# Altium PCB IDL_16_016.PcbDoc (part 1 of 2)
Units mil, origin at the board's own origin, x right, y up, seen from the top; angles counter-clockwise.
Board outline 4921.26 x 4921.26 mil, 4 copper layers (Top Layer - SIG1, MID1_GND, MID2_PWR, Bottom Layer - SIG2), stack 60.174 mil thick; 186 components, 167 nets, 650 pads, 188 vias.
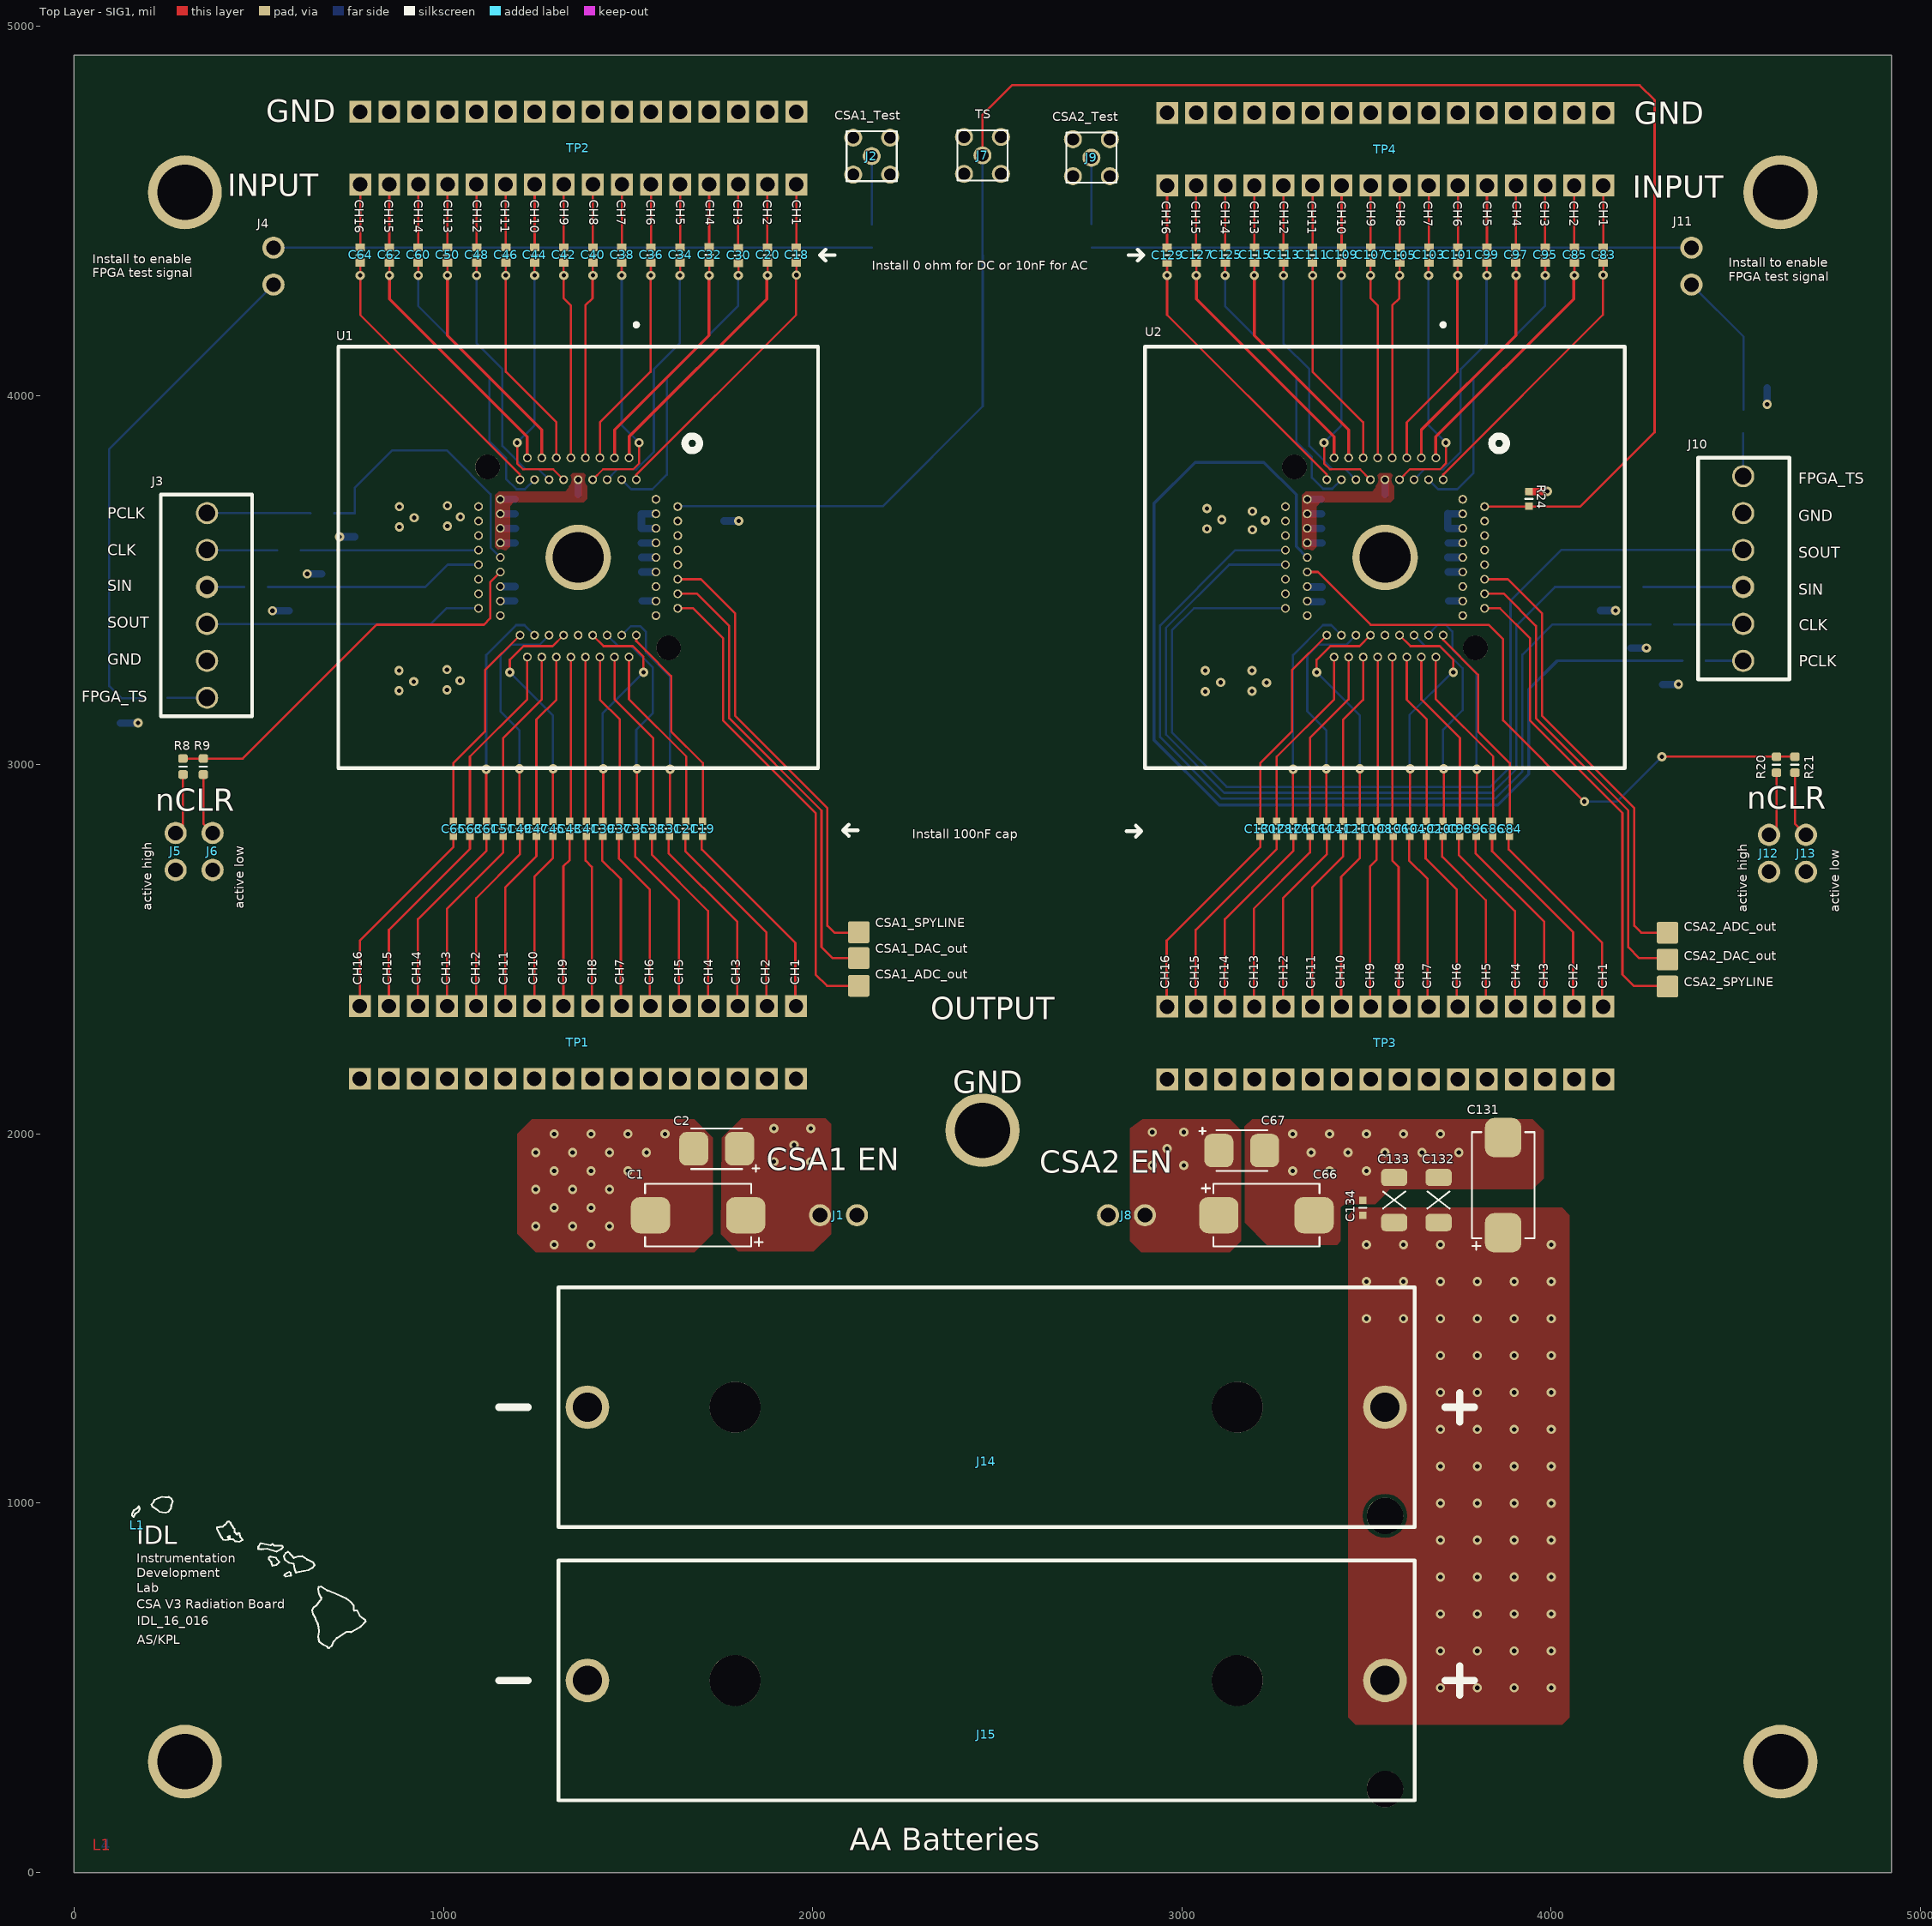
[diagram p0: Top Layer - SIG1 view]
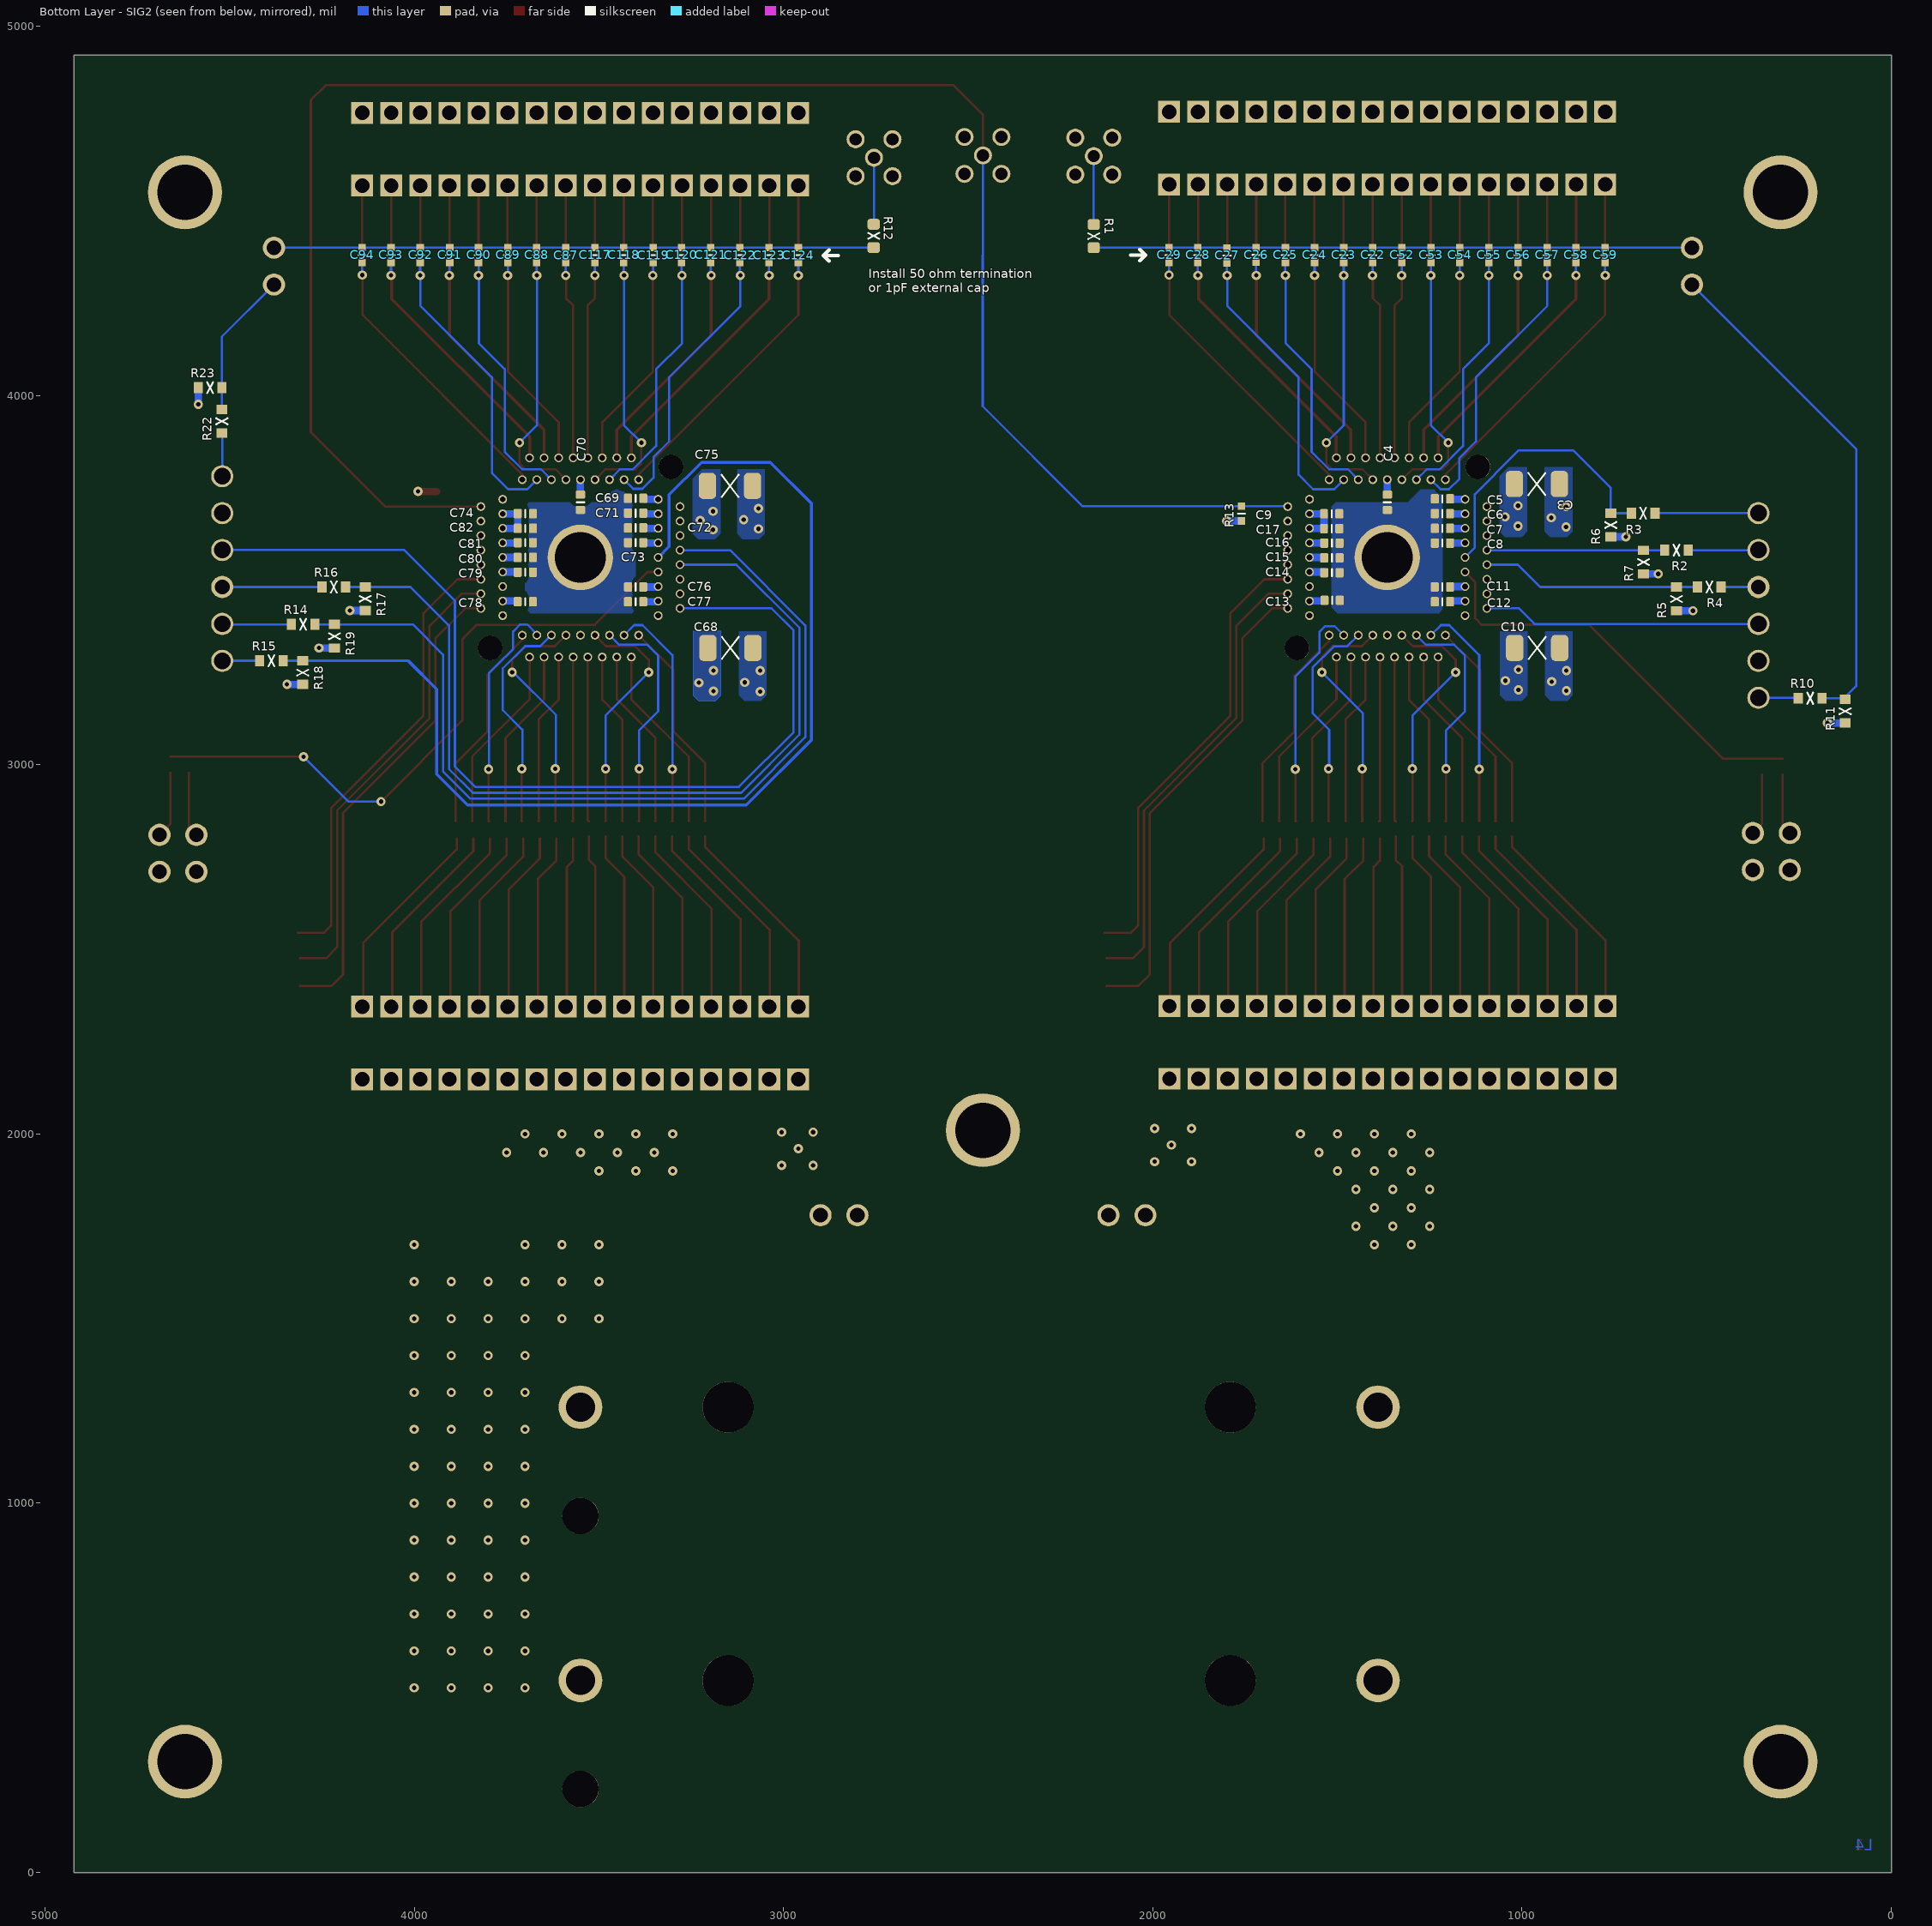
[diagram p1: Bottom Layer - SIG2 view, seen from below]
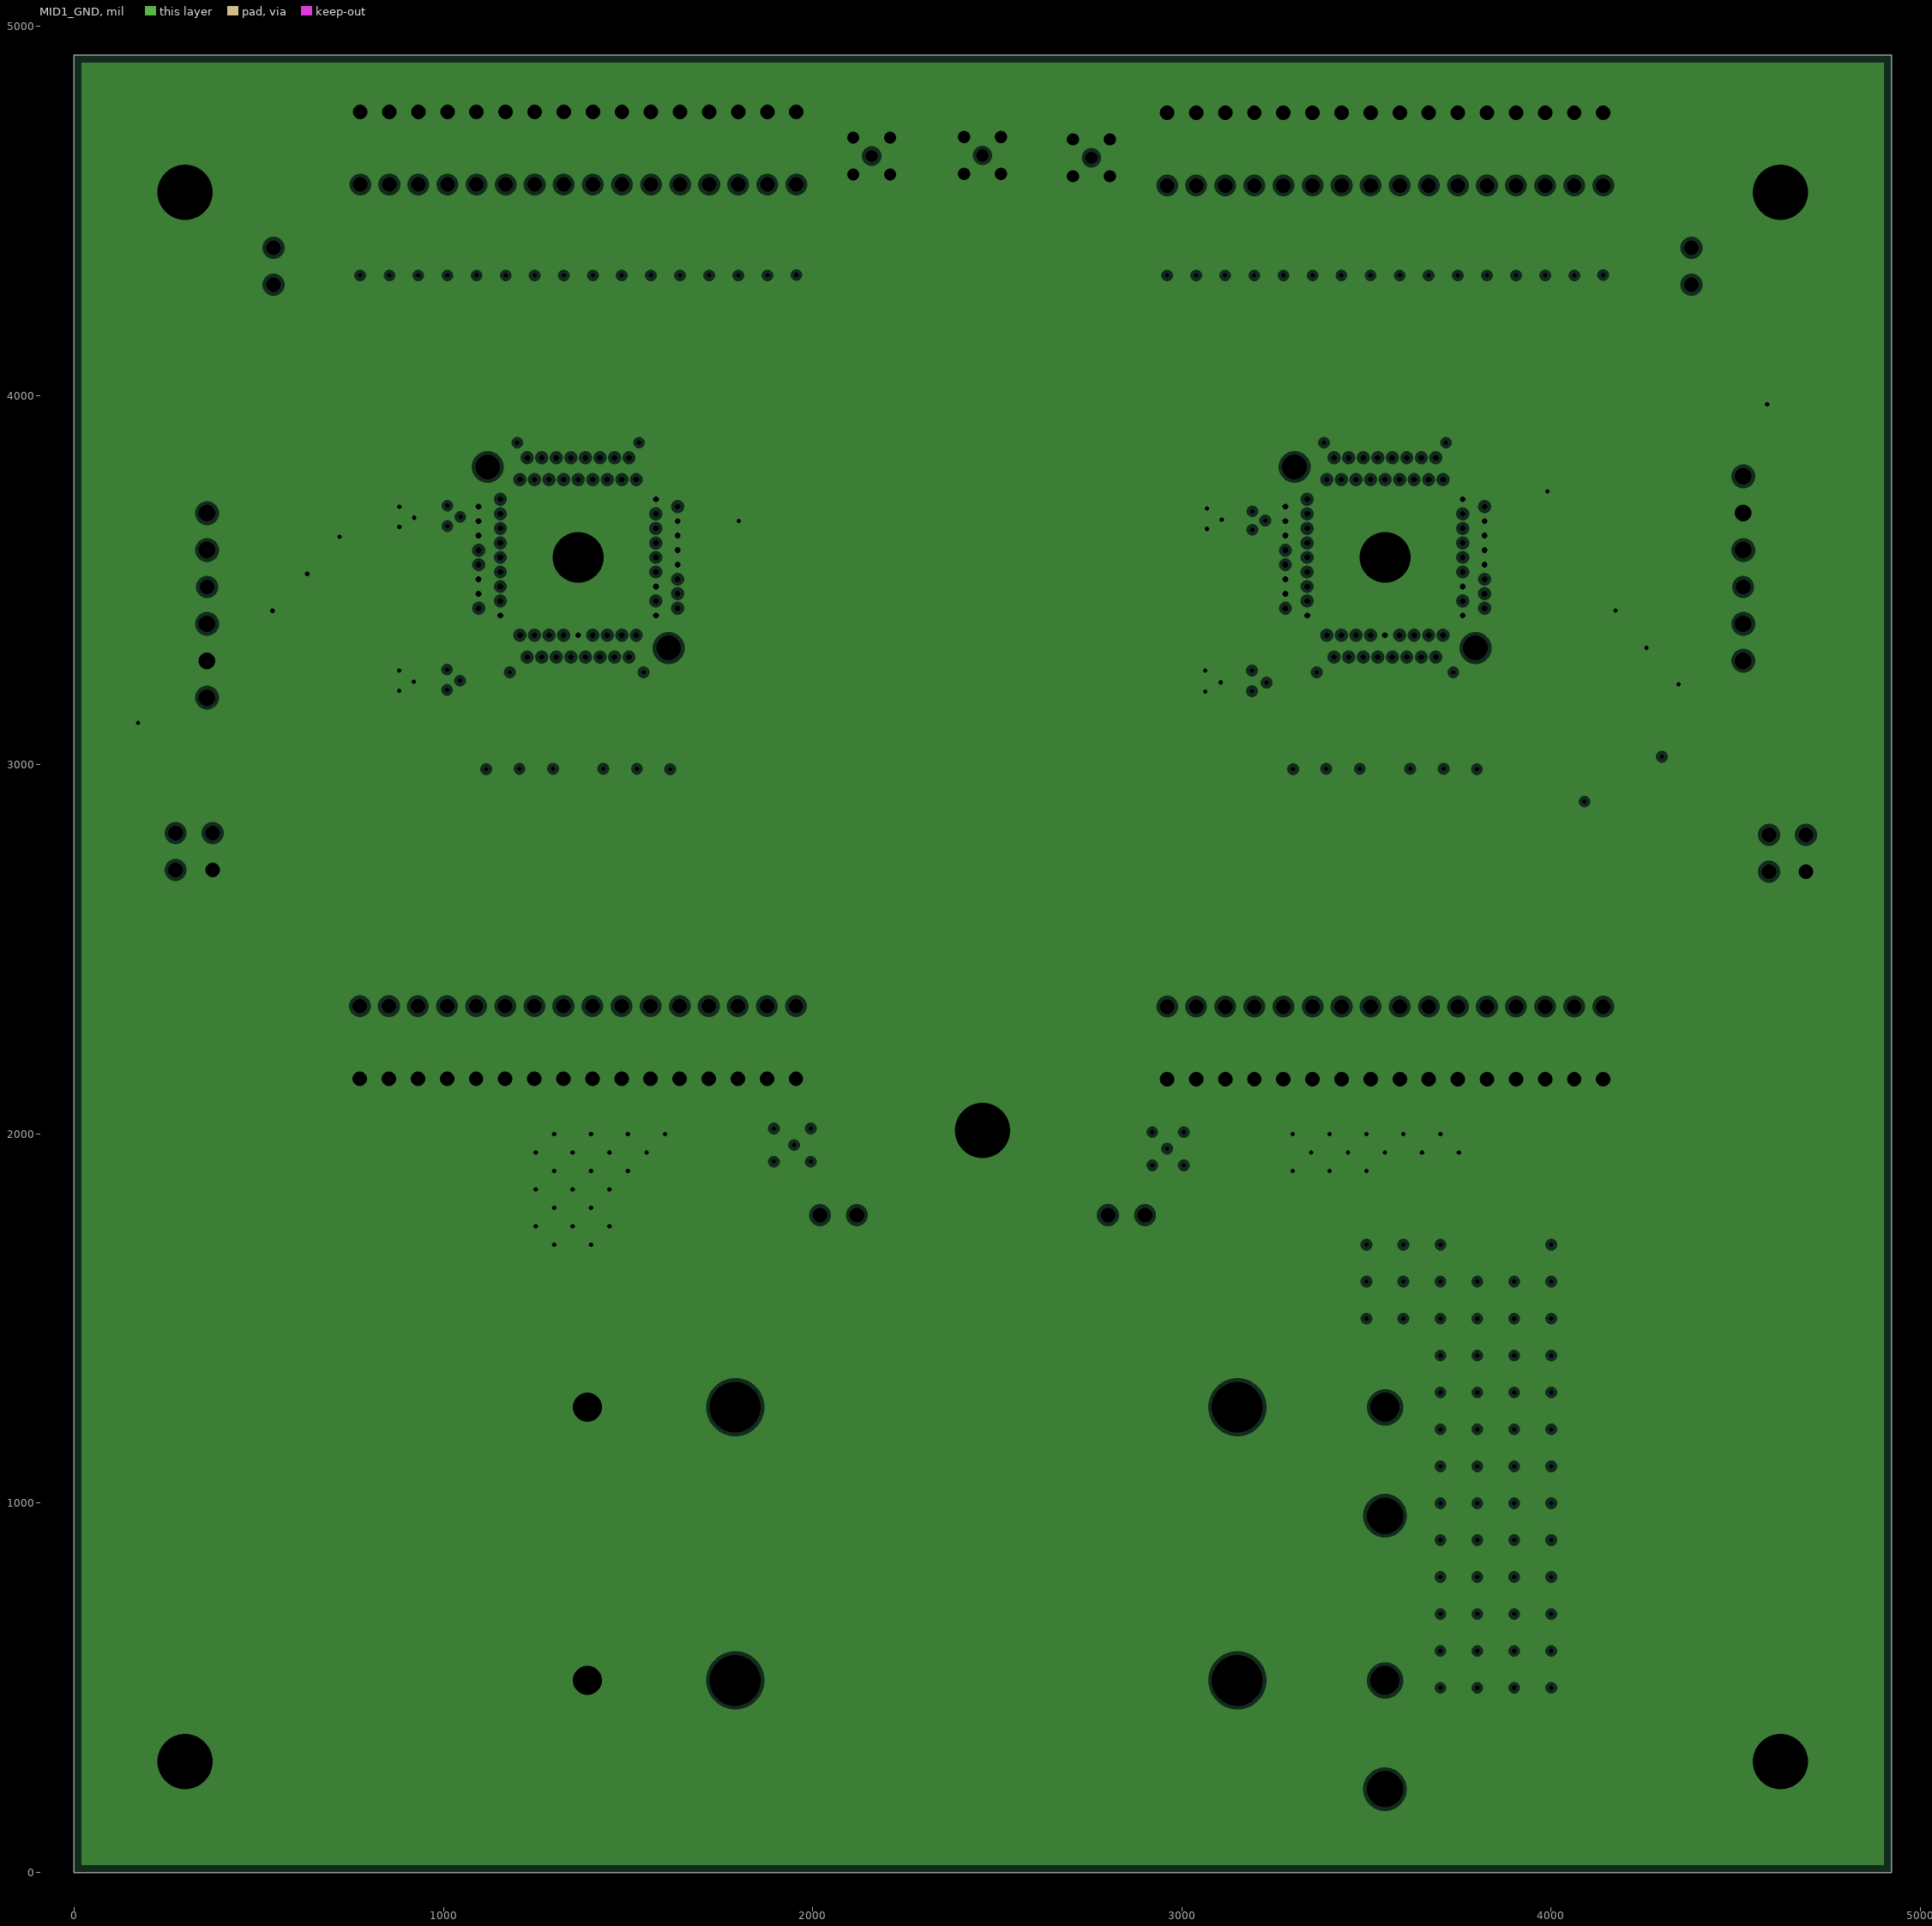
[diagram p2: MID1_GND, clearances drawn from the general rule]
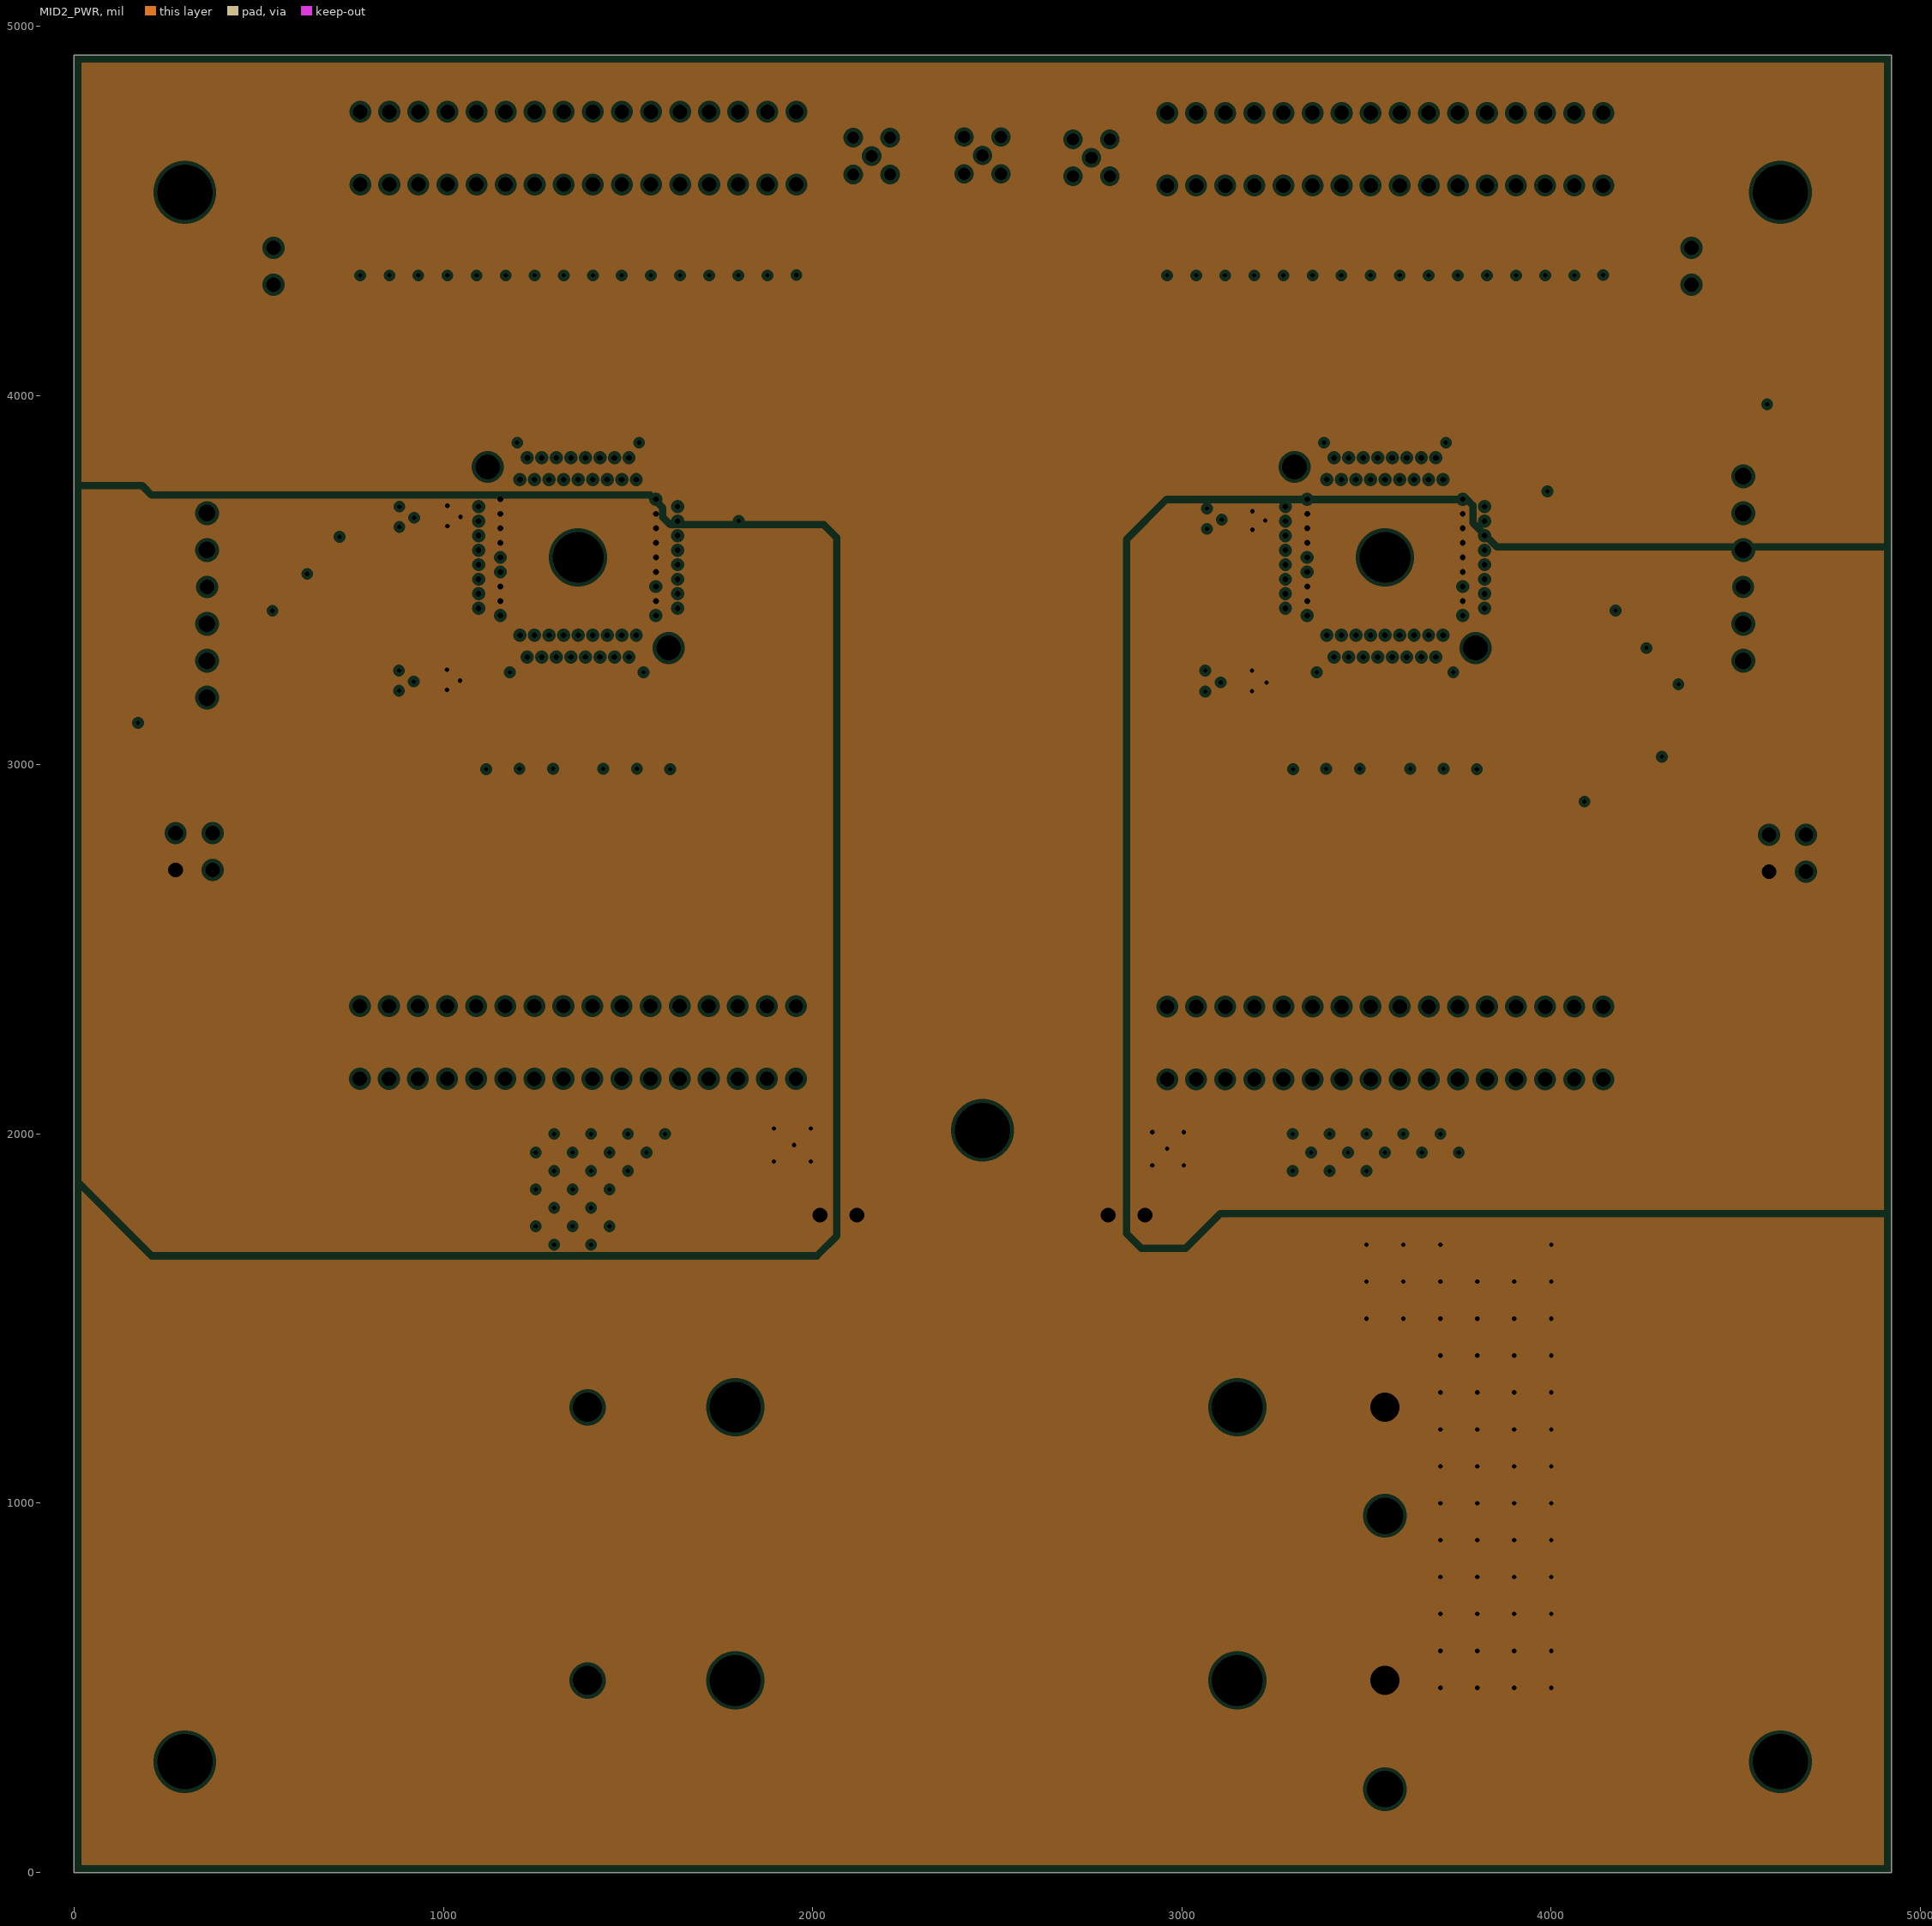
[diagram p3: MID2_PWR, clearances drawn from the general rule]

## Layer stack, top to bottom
Top Solder: solder mask 0.4, Solder Resist, Dk 3.5
Top Layer - SIG1: signal copper 1.378
Dielectric 1: prepreg 8, FR-4, Dk 4.65
MID1_GND: plane copper 0.709, net GND
Dielectric 2: core 40, FR-4, Dk 4.65
MID2_PWR: plane copper 0.709, net (Multiple Nets)
Dielectric 4: prepreg 8, FR-4, Dk 4.2
Bottom Layer - SIG2: signal copper 1.378
Bottom Solder: solder mask 0.4, Solder Resist, Dk 3.5

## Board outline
0,0 4921.26,0 4921.26,4921.26 0,4921.26

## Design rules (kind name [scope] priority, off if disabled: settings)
Clearance Clearance_Diff [InAnyDifferentialPair  or InNet('NetJ9_2') vs InNamedPolygon('Top_GND') or InNamedPolygon('Bot_GND3')] p1: gap=15
Clearance Clearance_RF [InNetClass('RF') or InNet('PWR') or InNet('NetJ9_2') or InNet('PWR1') or InNet('PWR2') vs InNamedPolygon('Top_GND') or InNamedPolygon('Bot_GND3')] p2: gap=20
Clearance Clearance_Poly [InNamedPolygon('L1_Top') or InNamedPolygon('L2_GND') or InNamedPolygon('L3_PWR') OR InNamedPolygon('L4_BOT')] p3: gap=10
Clearance Clearance_KeepOut [Iskeepout] p4 off: gap=20
Clearance [All] p5: gap=10
ComponentClearance [All] p1 off: gap=10 collisioncheckmode=3 verticalgap=10 showdistances=FALSE
DiffPairsRouting [All] p1: maxlimit=10 minlimit=6 mostfreqgap=6 toplayer_minwidth=6 toplayer_maxwidth=12 toplayer_prefwidth=8 bottomlayer_minwidth=6 bottomlayer_maxwidth=12 bottomlayer_prefwidth=8 maxuncoupledlength=500
Height [All] p1 off: minheight=0 maxheight=1000 prefheight=500
HoleSize [All] p1: absolutevalues=TRUE maxlimit=2500 minlimit=10 maxpercent=80.000 minpercent=20.000
MinimumSolderMaskSliver [All] p1: minsoldermaskwidth=5
NetAntennae [All] p1 off: netantennaetolerance=0
PlaneClearance [All] p1: clearance=10
PlaneConnect PlaneConnect_vIA [ISvIA] p1: planeconnectstyle=Direct reliefexpansion=20 reliefentries=4 reliefconductorwidth=10 reliefairgap=10
PlaneConnect [All] p2: planeconnectstyle=Direct reliefexpansion=12 reliefentries=4 reliefconductorwidth=15 reliefairgap=8
PolygonConnect PolygonConnect_Via [IsVia or InNet('GND') or InNet('PWR') or InNet('NetJ9_2') or InNet('PWR1') or InNet('PWR2')] p1: connectstyle=Direct reliefconductorwidth=10 reliefentries=4 polygonreliefangle="90 Angle" airgapwidth=10
PolygonConnect PolygonConnect_Main [All] p2: connectstyle=Relief reliefconductorwidth=12 reliefentries=4 polygonreliefangle="90 Angle" airgapwidth=10
RoutingVias [All] p1: holewidth=12 width=25 viastyle="Through Hole" minholewidth=6 minwidth=12 maxholewidth=25 maxwidth=50
SilkToSilkClearance [All] p1: silktosilkclearance=5
SilkToSolderMaskClearance SilkscreenOverComponentPads [IsPad] p1: minsilkscreentomaskgap=5 clearancetoexposedcopper=TRUE
SolderMaskExpansion [All] p1: expansion=2
Width Width_Logo [HasFootprint('ITECH_LOGO')] p1: maxlimit=10 minlimit=1 preferedwidth=2
Width [All] p2: maxlimit=150 minlimit=6 preferedwidth=8 minimp=50.000000 maximp=50.000000 favimp=50.000000
20 further rules are at their usual default settings.

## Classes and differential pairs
net class RF: CSA1_FPGA_TS CSA2_FPGA_TS GND NetC18_1 NetC18_2 NetC19_1 NetC19_2 NetC20_1 NetC20_2 NetC21_1 NetC21_2 NetC22_1 NetC23_1 NetC24_1 NetC25_1 NetC26_1 NetC27_1 NetC30_1 NetC31_1 NetC31_2 NetC32_1 NetC33_1 NetC33_2 NetC34_1 NetC35_1 NetC35_2 NetC36_1 NetC37_1 NetC37_2 NetC38_1 NetC39_1 NetC39_2 NetC40_1 NetC41_1 NetC41_2 NetC42_1 NetC42_2 NetC43_1 NetC43_2 NetC44_1 NetC44_2 NetC45_1 NetC45_2 NetC46_1 NetC46_2 NetC47_1 NetC47_2 NetC48_1 NetC48_2 NetC49_1 NetC49_2 NetC50_1 NetC50_2 NetC51_1 NetC51_2 NetC57_2 NetC58_2 NetC59_2 NetC60_1 NetC61_1 NetC61_2 NetC62_1 NetC63_1 NetC63_2 NetC64_1 NetC65_1 NetC65_2 NetC83_1 NetC83_2 NetC84_1 NetC84_2 NetC85_1 NetC85_2 NetC86_1 NetC86_2 NetC87_1 NetC88_1 NetC89_1 NetC90_1 NetC91_1 NetC92_1 NetC95_1 NetC96_1 NetC96_2 NetC97_1 NetC98_1 NetC98_2 NetC99_1 NetC100_1 NetC100_2 NetC101_1 NetC102_1 NetC102_2 NetC103_1 NetC104_1 NetC104_2 NetC105_1 NetC106_1 NetC106_2 NetC107_1 NetC107_2 NetC108_1 NetC108_2 NetC109_1 NetC109_2 NetC110_1 NetC110_2 NetC111_1 NetC111_2 NetC112_1 NetC112_2 NetC113_1 NetC113_2 NetC114_1 NetC114_2 NetC115_1 NetC115_2 NetC116_1 NetC116_2 NetC122_2 NetC123_2 NetC124_2 NetC125_1 NetC126_1 NetC126_2 NetC127_1 NetC128_1 NetC128_2 NetC129_1 NetC130_1 NetC130_2 NetJ2_1 NetJ9_1 "TEST SIGNAL"
component class CSAv3_A2_Socket2: C66 C67 C68 C69 C70 C71 C72 C73 C74 C75 C76 C77 C78 C79 C80 C81 C82 C83 C84 C85 C86 C87 C88 C89 C90 C91 C92 C93 C94 C95 C96 C97 C98 C99 C100 C101 C102 C103 C104 C105 C106 C107 C108 C109 C110 C111 C112 C113 C114 C115 C116 C117 C118 C119 C120 C121 C122 C123 C124 C125 C126 C127 C128 C129 C130 C131 C132 C133 C134 CSA2_ADC_out CSA2_DAC_out CSA2_SPYLINE J8 J9 J10 J11 J12 J13 J14 J15 R12 R13 R14 R15 R16 R17 R18 R19 R20 R21 R22 R23 TP3 TP4 U2
component class CSAv3_A1_Socket1: C1 C2 C3 C4 C5 C6 C7 C8 C9 C10 C11 C12 C13 C14 C15 C16 C17 C18 C19 C20 C21 C22 C23 C24 C25 C26 C27 C28 C29 C30 C31 C32 C33 C34 C35 C36 C37 C38 C39 C40 C41 C42 C43 C44 C45 C46 C47 C48 C49 C50 C51 C52 C53 C54 C55 C56 C57 C58 C59 C60 C61 C62 C63 C64 C65 CSA1_ADC_out J1 J2 J3 J4 J5 J6 J7 L1 R1 R2 R3 R4 R5 R6 R7 R8 R9 R10 R11 R24 TP1 TP2 U1

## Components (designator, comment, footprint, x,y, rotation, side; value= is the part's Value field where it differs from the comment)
C1 "220uF" CTC-D7343-43 1690,1780 r180 top
C2 "150uF" CTC-B3528-21 1740,1960 r180 top
C3 "10uF" CC1206N1R 960,3760 r180 bottom
C4 "4.7uF" CC0402N1R 1365,3710.59 r270 bottom
C5 "4.7uF" CC0402N1R 1215.67,3720 r0 bottom
C6 "4.7uF" CC0402N1R 1215.67,3680 r0 bottom
C7 "4.7uF" CC0402N1R 1215.67,3640 r0 bottom
C8 "4.7uF" CC0402N1R 1215.67,3600 r0 bottom
C9 "4.7uF" CC0402N1R 1515.63,3679.37 r180 bottom
C10 "10uF" CC1206N1R 958.98,3316.26 r0 bottom
C11 "4.7uF" CC0402N1R 1215.67,3481.26 r180 bottom
C12 "4.7uF" CC0402N1R 1215.67,3441.26 r180 bottom
C13 "4.7uF" CC0402N1R 1514.33,3445 r0 bottom
C14 "4.7uF" CC0402N1R 1515,3520 r0 bottom
C15 "4.7uF" CC0402N1R 1515,3560 r0 bottom
C16 "4.7uF" CC0402N1R 1515,3600 r0 bottom
C17 "4.7uF" CC0402N1R 1515.63,3639.37 r0 bottom
C18 "10nF" CC0402N1X 1956,4380 r270 top
C19 "100nF" CC0402RF1 1702,2826.26 r270 top
C20 "10nF" CC0402N1X 1878,4380 r270 top
C21 "100nF" CC0402RF1 1657,2826.26 r270 top
C22 "1.0pF" CC0402RF1 1405,4380 r90 bottom
C23 "1.0pF" CC0402RF1 1483,4380 r90 bottom
C24 "1.0pF" CC0402RF1 1562,4380 r90 bottom
C25 "1.0pF" CC0402RF1 1641,4380 r90 bottom
C26 "1.0pF" CC0402RF1 1720,4380.67 r90 bottom
C27 "1.0pF" CC0402RF1 1799,4379 r90 bottom
C28 "1.0pF" CC0402RF1 1878,4380 r90 bottom
C29 "1.0pF" CC0402RF1 1956,4380 r90 bottom
C30 "10nF" CC0402N1X 1799,4379 r270 top
C31 "100nF" CC0402RF1 1612,2826.26 r270 top
C32 "10nF" CC0402N1X 1720,4380.67 r270 top
C33 "100nF" CC0402RF1 1567,2826.26 r270 top
C34 "10nF" CC0402N1X 1641,4380 r270 top
C35 "100nF" CC0402RF1 1522,2826.26 r270 top
C36 "10nF" CC0402N1X 1562,4380 r270 top
C37 "100nF" CC0402RF1 1477,2826.26 r270 top
C38 "10nF" CC0402N1X 1483,4380 r270 top
C39 "100nF" CC0402RF1 1432,2826.26 r270 top
C40 "10nF" CC0402N1X 1405,4380 r270 top
C41 "100nF" CC0402RF1 1387,2826.26 r270 top
C42 "10nF" CC0402N1X 1326,4380.33 r270 top
C43 "100nF" CC0402RF1 1342,2826.26 r270 top
C44 "10nF" CC0402N1X 1247,4380 r270 top
C45 "100nF" CC0402RF1 1297,2826.26 r270 top
C46 "10nF" CC0402N1X 1169,4380 r270 top
C47 "100nF" CC0402RF1 1252,2826.26 r270 top
C48 "10nF" CC0402N1X 1090,4380 r270 top
C49 "100nF" CC0402RF1 1207,2826.26 r270 top
C50 "10nF" CC0402N1X 1011,4380 r270 top
C51 "100nF" CC0402RF1 1162,2826.26 r270 top
C52 "1.0pF" CC0402RF1 1326,4380 r270 bottom
C53 "1.0pF" CC0402RF1 1247,4380 r270 bottom
C54 "1.0pF" CC0402RF1 1169,4380 r270 bottom
C55 "1.0pF" CC0402RF1 1090,4380 r270 bottom
C56 "1.0pF" CC0402RF1 1011,4380 r270 bottom
C57 "1.0pF" CC0402RF1 932,4380 r270 bottom
C58 "1.0pF" CC0402RF1 854,4380 r270 bottom
C59 "1.0pF" CC0402RF1 775,4380 r270 bottom
C60 "10nF" CC0402N1X 932,4380 r270 top
C61 "100nF" CC0402RF1 1117,2826.26 r270 top
C62 "10nF" CC0402N1X 854,4380 r270 top
C63 "100nF" CC0402RF1 1072,2826.26 r270 top
C64 "10nF" CC0402N1X 775,4380 r270 top
C65 "100nF" CC0402RF1 1027,2826.26 r270 top
C66 "220uF" CTC-D7343-43 3228.94,1780 r0 top
C67 "150uF" CTC-B3528-21 3162.01,1955 r0 top
C68 "10uF" CC1206N1R 3143.98,3316.26 r180 bottom
C69 "4.7uF" CC0402N1R 3400.67,3721.26 r0 bottom
C70 "4.7uF" CC0402N1R 3550,3710.59 r270 bottom
C71 "4.7uF" CC0402N1R 3400.67,3681.26 r0 bottom
C72 "4.7uF" CC0402N1R 3400.67,3641.26 r0 bottom
C73 "4.7uF" CC0402N1R 3400.67,3601.26 r0 bottom
C74 "4.7uF" CC0402N1R 3699.33,3680 r180 bottom
C75 "10uF" CC1206N1R 3145,3755 r0 bottom
C76 "4.7uF" CC0402N1R 3400.67,3481.26 r180 bottom
C77 "4.7uF" CC0402N1R 3400.67,3441.26 r180 bottom
C78 "4.7uF" CC0402N1R 3699.33,3441.26 r0 bottom
C79 "4.7uF" CC0402N1R 3699.33,3521.26 r0 bottom
C80 "4.7uF" CC0402N1R 3699.33,3561.26 r0 bottom
C81 "4.7uF" CC0402N1R 3699.33,3601.26 r0 bottom
C82 "4.7uF" CC0402N1R 3699.33,3640 r0 bottom
C83 "10nF" CC0402N1X 4141,4380 r270 top
C84 "100nF" CC0402RF1 3887,2826.26 r270 top
C85 "10nF" CC0402N1X 4063,4380 r270 top
C86 "100nF" CC0402RF1 3842,2826.26 r270 top
C87 "1.0pF" CC0402RF1 3590,4379.92 r90 bottom
C88 "1.0pF" CC0402RF1 3669,4380 r90 bottom
C89 "1.0pF" CC0402RF1 3747,4380 r90 bottom
C90 "1.0pF" CC0402RF1 3826,4380 r90 bottom
C91 "1.0pF" CC0402RF1 3904,4380 r90 bottom
C92 "1.0pF" CC0402RF1 3984,4380 r90 bottom
C93 "1.0pF" CC0402RF1 4063,4380 r90 bottom
C94 "1.0pF" CC0402RF1 4141,4380 r90 bottom
C95 "10nF" CC0402N1X 3984,4380 r270 top
C96 "100nF" CC0402RF1 3797,2826.26 r270 top
C97 "10nF" CC0402N1X 3904,4380 r270 top
C98 "100nF" CC0402RF1 3752,2826.26 r270 top
C99 "10nF" CC0402N1X 3826,4380 r270 top
C100 "100nF" CC0402RF1 3707,2826.26 r270 top
C101 "10nF" CC0402N1X 3747,4380 r270 top
C102 "100nF" CC0402RF1 3662,2826.26 r270 top
C103 "10nF" CC0402N1X 3669,4380 r270 top
C104 "100nF" CC0402RF1 3617,2826.26 r270 top
C105 "10nF" CC0402N1X 3590,4379.92 r270 top
C106 "100nF" CC0402RF1 3572,2826.26 r270 top
C107 "10nF" CC0402N1X 3511,4380 r270 top
C108 "100nF" CC0402RF1 3527,2826.26 r270 top
C109 "10nF" CC0402N1X 3433,4380 r270 top
C110 "100nF" CC0402RF1 3482,2826.26 r270 top
C111 "10nF" CC0402N1X 3353,4380 r270 top
C112 "100nF" CC0402RF1 3437,2826.26 r270 top
C113 "10nF" CC0402N1X 3276,4380 r270 top
C114 "100nF" CC0402RF1 3392,2826.26 r270 top
C115 "10nF" CC0402N1X 3197,4380 r270 top
C116 "100nF" CC0402RF1 3347,2826.26 r270 top
C117 "1.0pF" CC0402RF1 3511,4380 r270 bottom
C118 "1.0pF" CC0402RF1 3433,4380 r270 bottom
C119 "1.0pF" CC0402RF1 3353,4379.92 r270 bottom
C120 "1.0pF" CC0402RF1 3276,4380 r270 bottom
C121 "1.0pF" CC0402RF1 3197,4380 r270 bottom
C122 "1.0pF" CC0402RF1 3118,4379.92 r270 bottom
C123 "1.0pF" CC0402RF1 3039,4379.92 r270 bottom
C124 "1.0pF" CC0402RF1 2960,4379.92 r270 bottom
C125 "10nF" CC0402N1X 3118,4380 r270 top
C126 "100nF" CC0402RF1 3302,2826.26 r270 top
C127 "10nF" CC0402N1X 3039,4380 r270 top
C128 "100nF" CC0402RF1 3257,2826.26 r270 top
C129 "10nF" CC0402N1X 2960,4379.92 r270 top
C130 "100nF" CC0402RF1 3212,2826.26 r270 top
C131 "330uF" CTC-D7343-43 3870,1861.26 r90 top
C132 "10uF" CC1206N1R 3695,1821.26 r270 top
C133 "10uF" CC1206N1R 3575,1821.26 r270 top
C134 "100nF" CC0402RF1 3490,1800 r270 top
CSA1_ADC_out "SP1.5S" SP1.5SQ 2125,2401.26 r90 top
CSA1_DAC_out "SP1.5S" SP1.5SQ 2125,2476.26 r90 top
CSA1_SPYLINE "SP1.5S" SP1.5SQ 2125,2546.26 r90 top
CSA2_ADC_out "SP1.5S" SP1.5SQ 4315,2545 r180 top
CSA2_DAC_out "SP1.5S" SP1.5SQ 4315,2472.17 r180 top
CSA2_SPYLINE "SP1.5S" SP1.5SQ 4315,2399.33 r180 top
J1 "2pin_Jumper" 2PIN_JUMPER 2070,1780 r180 top
J2 "MMCX" MMCX_VERTICAL_THROUGH_HOLE 2159.89,4647.99 r0 top
J3 "Male" "Molex 6POS" 360,3681.26 r270 top
J4 "2pin_Jumper" 2pin_jumper 540,4350 r270 top
J5 "2pin_Jumper" 2PIN_JUMPER 275,2765 r90 top
J6 "2pin_Jumper" 2pin_jumper 375,2765 r270 top
J7 "MMCX" MMCX_VERTICAL_THROUGH_HOLE 2460,4650 r0 top
J8 "2pin_Jumper" 2PIN_JUMPER 2850,1780 r0 top
J9 "MMCX" MMCX_VERTICAL_THROUGH_HOLE 2755,4643.74 r0 top
J10 "Male" "Molex 6POS" 4520,3281.26 r90 top
J11 "2pin_Jumper" 2pin_jumper 4380,4350 r270 top
J12 "2pin_Jumper" 2PIN_JUMPER 4590,2760 r90 top
J13 "2pin_Jumper" 2pin_jumper 4690,2760 r270 top
J14 "AA Batt holder" Batt_pack_AA 1390.16,1260 r0 top
J15 "AA Batt holder" Batt_pack_AA 1390.16,520 r0 top
L1 "IDLab Logo" "IDLab logo" 170,940 r0 top
R1 "0R0" RC0603N1R 2160,4431.5 r270 bottom
R2 "30k" RC0603RF1 582,3580.74 r0 bottom
R3 "30k" RC0603RF1 672,3681 r0 bottom
R4 "30k" RC0603RF1 493,3481 r0 bottom
R5 "20k" RC0603RF1 582,3449 r90 bottom
R6 "20k" RC0603RF1 760,3649 r90 bottom
R7 "20k" RC0603RF1 671,3548.74 r90 bottom
R8 "4K7" RC0402N1R 295,2995 r270 top
R9 "4K7" RC0402N1R 350,2995 r90 top
R10 "30k" RC0603RF1 220,3180 r0 bottom
R11 "20k" RC0603RF1 125,3145 r270 bottom
R12 "0R0" RC0603N1R 2756,4432 r270 bottom
R13 "50R" RC0402RF1 1760,3680 r90 bottom
R14 "30k" RC0603RF1 4301,3380 r180 bottom
R15 "30k" RC0603RF1 4387,3281.5 r180 bottom
R16 "30k" RC0603RF1 4218,3481.26 r180 bottom
R17 "20k" RC0603RF1 4133,3449.26 r90 bottom
R18 "20k" RC0603RF1 4302,3249.5 r90 bottom
R19 "20k" RC0603RF1 4216,3348 r90 bottom
R20 "4K7" RC0402N1R 4610,3000 r270 top
R21 "4K7" RC0402N1R 4660,3000 r90 top
R22 "30k" RC0603RF1 4521,3930 r270 bottom
R23 "20k" RC0603RF1 4553,4021 r0 bottom
R24 "50R" RC0402RF1 3940,3720 r270 top
TP1 "16X2 TP" "16X2 TP" 773.82,2149.41 r0 top locked
TP2 "16X2 TP" "16X2 TP" 774.89,4571.14 r0 top locked
TP3 "16X2 TP" "16X2 TP" 2960,2148.15 r0 top locked
TP4 "16X2 TP" "16X2 TP" 2960,4568.15 r0 top locked
U1 "CSA_V3_SOCKET" SOCKET_QFN-68BT-0.5-01 1365,3561.26 r270 top locked
U2 "CSA_V3_SOCKET" SOCKET_QFN-68BT-0.5-01 3550,3561.26 r270 top locked

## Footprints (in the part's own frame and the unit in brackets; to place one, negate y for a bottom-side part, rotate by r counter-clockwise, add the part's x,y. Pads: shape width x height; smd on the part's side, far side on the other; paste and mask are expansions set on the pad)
2PIN_JUMPER [mil]
  round 60 hole 40: 1(-50,0) 2(50,0)
  body extent -100,-50 100,50, height 500
2pin_jumper [mil]
  round 60 hole 40: 1(-50,0) 2(50,0)
  body extent -100,-50 100,50, height 500
"16X2 TP" [mm]
  rect 1.5x1.5 hole 1: 1(30,0) 2(28,0) 3(26,0) 4(24,0) 5(22,0) 6(20,0) 7(18,0) 8(16,0) 9(14,0) 10(12,0) 11(10,0) 12(8,0) 13(6,0) 14(4,0) 15(2,0) 16(0,0) 17(0,5) 18(2,5) 19(4,5) 20(6,5) 21(8,5) 22(10,5) 23(12,5) 24(14,5) 25(16,5) 26(18,5) 27(20,5) 28(22,5) 29(24,5) 30(26,5) 31(28,5) 32(30,5)
Batt_pack_AA [mm] "HOLDER BATTERY 1/AA CELL PC MNT"
  round 3 hole 2: 1(0,0) 2(54.86,0)
  round 2.5 hole 2.5 unplated: 3(54.86,-7.47)
  round 3.5 hole 3.5 unplated: 4(10.16,0) 5(44.7,0)
  silkscreen extent -6.1,-8.25 61,8.25, body extent -2,-8.25 56.9,8.25, height 19
CC0402N1R [mm] "Chip capacitor 0402 ROUND pad"
  rrect30% 0.55x0.65 smd mask+0.025: 1(-0.525,0) 2(0.525,0)
  silkscreen extent 0,-0.25 0,0.25, body extent -0.51,-0.25 0.51,0.25, height 0.5
CC0402N1X [mm] "Chip capacitor 0402"
  rect 0.55x0.65 smd mask+0.025: 1(-0.525,0) 2(0.525,0)
  silkscreen extent 0,-0.25 0,0.25, body extent -0.51,-0.25 0.51,0.25, height 0.5
CC0402RF1 [mil] "Chip capacitor 0402 RF pad"
  rect 20x20 smd: 1(-20,0) 2(20,0)
  silkscreen extent 0,-10 0,10, body extent -20,-10 20,10, height 20
CC1206N1R [mm] "Chip capacitor 1206 ROUNDED PAD"
  rrect50% 1.2x1.8 smd: 1(-1.55,0) 2(1.55,0)
  silkscreen extent -0.58,-0.76 0.58,0.76, body extent -1.6,-0.8 1.6,0.8, height 1.35
CTC-B3528-21 [mm] "Capacitor Tantal Chip B - 3528, H=1.9mm"
  rrect50% 2x2.3 smd: 1(-1.575,0) 2(1.575,0)
  silkscreen extent -2.92,-1.4 1.75,1.58, body extent -1.92,-1.4 1.92,1.4, height 1.91
CTC-D7343-43 [mm] "Capacitor Tantal Chip D - 7343, H=4.3mm"
  rrect50% 2.7x2.5 smd: 1(-3.275,0) 2(3.275,0)
  silkscreen extent -4.45,-2.15 3.65,2.15, body extent -4,-2.15 4,2.15, height 4.31
"IDLab logo" [mil]
  silkscreen extent -13,-332 619,77
MMCX_VERTICAL_THROUGH_HOLE [mm]
  round 1.24 hole 0.84: 1(0,0) 2(-1.27,-1.27) 3(1.27,-1.27) 4(1.27,1.27) 5(-1.27,1.27)
  silkscreen extent -1.73,-1.73 1.73,1.73, body extent -1.73,-1.73 1.73,1.73, height 4.42
"Molex 6POS" [mil] "CONN HEADER 6POS 2.54mm VERT TIN"
  round 60 hole 45: 1(0,0) 2(100,0) 4(300,0) 5(400,0) 6(500,0)
  round 60 hole 40: 3(200,0)
  silkscreen extent -50,-125 550,122, body extent -47,-128 547,122, height 420
RC0402N1R [mm] "Chip capacitor 0402 ROUNDED PAD"
  rrect50% 0.6x0.65 smd: 1(-0.55,0) 2(0.55,0)
  silkscreen extent 0,-0.25 0,0.25, body extent -0.51,-0.25 0.51,0.25, height 0.36
RC0402RF1 [mil] "Chip resistor 0402 RF pad"
  rect 20x20 smd: 1(-20,0) 2(20,0)
  silkscreen extent 0,-10 0,10, body extent -20,-10 20,10, height 14
RC0603N1R [mm] "Chip resistor 0603 ROUNDED PAD"
  rrect50% 0.75x0.85 smd: 1(-0.8,0) 2(0.8,0)
  silkscreen extent -0.2,-0.38 0.2,0.38, body extent -0.8,-0.4 0.8,0.4, height 0.46
RC0603RF1 [mil] "Chip resistor 0603 RF pad"
  rect 25x30 smd: 1(-32,0) 2(32,0)
  silkscreen extent -8,-15 8,15, body extent -31,-16 31,16, height 18
SOCKET_QFN-68BT-0.5-01 [mm] "QFN-68BT-0.5-01 QFN68 MLP68 MLF68 IC Program Programmer Programming Adapter"
  round 0.6 hole 0.4: 1(-5.35,4) 2(-6.85,3.5) 3(-5.35,3) 4(-6.85,2.5) 5(-5.35,2) 6(-6.85,1.5) 7(-5.35,1) 8(-6.85,0.5) 9(-5.35,0) 10(-6.85,-0.5) 11(-5.35,-1) 12(-6.85,-1.5) 13(-5.35,-2) 14(-6.85,-2.5) 15(-5.35,-3) 16(-6.85,-3.5) 17(-5.35,-4) 18(-4,-5.35) 19(-3.5,-6.85) 20(-3,-5.35) 21(-2.5,-6.85) 22(-2,-5.35) 23(-1.5,-6.85) 24(-1,-5.35) 25(-0.5,-6.85) 26(0,-5.35) 27(0.5,-6.85) 28(1,-5.35) 29(1.5,-6.85) 30(2,-5.35) 31(2.5,-6.85) 32(3,-5.35) 33(3.5,-6.85) 34(4,-5.35) 35(5.35,-4) 36(6.85,-3.5) 37(5.35,-3) 38(6.85,-2.5) 39(5.35,-2) 40(6.85,-1.5) 41(5.35,-1) 42(6.85,-0.5) 43(5.35,0) 44(6.85,0.5) 45(5.35,1) 46(6.85,1.5) 47(5.35,2) 48(6.85,2.5) 49(5.35,3) 50(6.85,3.5) 51(5.35,4) 52(4,5.35) 53(3.5,6.85) 54(3,5.35) 55(2.5,6.85) 56(2,5.35) 57(1.5,6.85) 58(1,5.35) 59(0.5,6.85) 60(0,5.35) 61(-0.5,6.85) 62(-1,5.35) 63(-1.5,6.85) 64(-2,5.35) 65(-2.5,6.85) 66(-3,5.35) 67(-3.5,6.85) 68(-4,5.35)
  round 4.5 hole 3.5: 69(0,0)
  round 1.7 hole 1.7 unplated: 70(-6.225,-6.225) 71(6.225,6.225)
  silkscreen extent -16.12,-16.5 14.5,16.5, body extent -14.5,-16.5 14.5,16.5, height 16.7
SP1.5SQ [mm] "Solder Pad 1.5mm SMT"
  rrect20% 1.5x1.5 smd: 1(0,0)

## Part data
C1 C66: library part CAPT7343_220U_6.3V, "220µF 6.3V Aluminum - Polymer Capacitors"
C2 C67: library part CAPT3528_150U6V3R0.5, "150µF Molded Tantalum Capacitors 6.3V 1411"
C3 C10 C68 C75 C132 C133: library part CAPCC1206_10U_16VX7R, "10µF 16V Ceramic Capacitor X7R 1206"
C4 C5 C6 C7 C8 C9 C11 C12 C13 C14 C15 C16 C17 C69 C70 C71 C72 C73 C74 C76 C77 C78 C79 C80 C81 C82: library part CAPCC0402_4.7uF_6.3V, "4.7µF ±10% 6.3V X7R Ceramic Capacitor"
C18 C20 C30 C32 C34 C36 C38 C40 C42 C44 C46 C48 C50 C60 C62 C64 C83 C85 C95 C97 C99 C101 C103 C105 C107 C109 C111 C113 C115 C125 C127 C129: library part CAPCC0402_1_10.0N_50VX7R, "Capacitor chip ceramic 0402 50V X7R"
C19 C21 C31 C33 C35 C37 C39 C41 C43 C45 C47 C49 C51 C61 C63 C65 C84 C86 C96 C98 C100 C102 C104 C106 C108 C110 C112 C114 C116 C126 C128 C130 C134: library part CAP0402_100N_50VX7R, "Capacitor chip ceramic 0402 50V X7R"
C22 C23 C24 C25 C26 C27 C28 C29 C52 C53 C54 C55 C56 C57 C58 C59 C87 C88 C89 C90 C91 C92 C93 C94 C117 C118 C119 C120 C121 C122 C123 C124: library part CAP0402_1P_50VNP0, "Capacitor chip ceramic 0402 50V NPO"
C131: library part CAPT7343_330U_16V, "330µF Molded Tantalum - Polymer Capacitors 16V"
CSA1_ADC_out CSA1_DAC_out CSA1_SPYLINE CSA2_ADC_out CSA2_DAC_out CSA2_SPYLINE: "Wire solder pin 1.5mm"
J1 J4 J5 J6 J8 J11 J12 J13: "2 Positions Header, Unshrouded, Breakaway Connector 0.100\" (2.54mm) Through Hole Tin"
J2 J7 J9: "CONN MMCX JACK STR 50 OHM PCB"
J3 J10: library part "CONN_6pin_Molex 2.54mm", "6 Positions Header, Unshrouded Connector 0.100\" (2.54mm) Through Hole Tin"
J14 J15: library part Batt_pack_AA, "HOLDER BATTERY 1/AA CELL PC MNT"
R1 R12: library part RES0603-0R0-1%100PPM, "RES SMD 0.0OHM JUMPER 1/10W 0603"
R2 R3 R4 R10 R14 R15 R16 R22: library part RES0603-30K-1%100PPM, "RES SMD 30K OHM 1% 1/10W 0603"
R5 R6 R7 R11 R17 R18 R19 R23: library part RES0603-20K-1%100PPM, "RES SMD 20K OHM 1% 1/10W 0603"
R8 R9 R20 R21: library part RES0402-4.7K-1%100PPM, "RES SMD 4.7K OHM 1% 1/10W 0402"
R13 R24: library part RES0402-50R-1%100PPM, "RES SMD 49.9 OHM 1% 1/16W 0402"
TP1 TP2 TP3 TP4: library part "TP 16X2", "16X2 TESTPOINTs"
U1 U2: library part CSA_V3_socket, "Enplas IC Test & Burn-in Socket, for QFN68, MLP68, MLF68 package"

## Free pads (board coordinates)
  round 200 hole 150: 1(300,4550) 2(4621,4550) 3(4621,300) 4(300,300) 5(2460,2010)

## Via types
v1: diameter 25, hole 12, Top Layer - SIG1 to Bottom Layer - SIG2, 188 vias

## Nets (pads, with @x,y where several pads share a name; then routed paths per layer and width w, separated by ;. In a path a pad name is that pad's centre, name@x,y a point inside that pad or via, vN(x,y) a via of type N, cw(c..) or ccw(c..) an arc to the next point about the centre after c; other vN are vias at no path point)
CSA1_CLK_3: R2.2 R7.2 U1.25 | length 481.3
  Bottom Layer - SIG2 w6: R2.2@614,3580.95 U1.25@1095.32,3580.95
CSA1_FPGA_TS: C22.2 C23.2 C24.2 C25.2 C26.2 C27.2 C28.2 C29.2 C52.1 C53.1 C54.1 C55.1 C56.1 C57.1 C58.1 C59.1 J4.1 R1.2 | length 1620
  Bottom Layer - SIG2 w6: J4.1@540,4400 C59.1@775,4400 C58.1@854,4400 C57.1@932,4400 C56.1@1011,4400 C55.1@1090,4400 C54.1@1169,4400 C53.1@1247,4400 C52.1@1326,4400 C24.2@1562,4400 C25.2@1641,4400 C29.2@1956,4400 R1.2@2160,4400
CSA1_NCLR_3: R8.1 R9.2 U1.28 | length 1126.4
  Top Layer - SIG1 w6: R8.1@295,3016.65 R9.2@350,3016.65 456.65,3016.65 819,3379 1110,3379 1127,3396 1127,3494.52 U1.28@1154.37,3521.89
CSA1_PCLK_3: R3.2 R6.2 U1.26 | length 766.4
  Bottom Layer - SIG2 w6: R3.2@704,3681 R6.2@760,3681 760,3750 861,3851 1010,3851 1073.46,3787.54 1073.46,3787.09 1128,3732.55 1128,3587.63 U1.26@1154.37,3561.26
CSA1_SIN_3: R4.2 R5.2 U1.27 | length 595.3
  Bottom Layer - SIG2 w6: R4.2@525,3481.26 951.26,3481.26 1011.58,3541.58 U1.27@1095.32,3541.58
CSA1_SOUT: J3.4 U1.33 | length 752.8
  Bottom Layer - SIG2 w6: J3.4@360,3381.26 966.26,3381.26 1008.46,3423.46 U1.33@1095.32,3423.47
CSA2_CLK_4: R14.2 R19.2 U2.25 | length 2504
  Bottom Layer - SIG2 w6: U2.25@3280.32,3580.95 3144.69,3580.95 2941,3377.25 2941,3074.75 3107.75,2908 3848.25,2908 3922,2981.75 3922,3298 4004,3380 R19.2@4216,3380 R14.2@4269,3380
CSA2_FPGA_TS: C87.2 C88.2 C89.2 C90.2 C91.2 C92.2 C93.2 C94.2 C117.1 C118.1 C119.1 C120.1 C121.1 C122.1 C123.1 C124.1 J11.1 R12.2 | length 1623.5
  Bottom Layer - SIG2 w6: R12.2@2756.5,4400 3039,4400 C121.1@3197,4400 C120.1@3276,4400 C118.1@3433,4400 C89.2@3747,4400 C91.2@3904,4400 C92.2@3984,4400 C93.2@4063,4400 C94.2@4141,4400 J11.1@4380,4400
CSA2_NCLR_4: R20.1 R21.2 U2.28 | length 1757.5
  Top Layer - SIG1 w6: U2.28@3339.37,3521.89 3368.11,3521.89 3511.03,3378.97 3831.03,3378.97 3870,3340 3870,3120 v1(4090,2900) ; v1(4300,3021.65) R20.1@4610,3021.65 R21.2@4660,3021.65
  Bottom Layer - SIG2 w6: v1(4090,2900) 4178.35,2900 v1(4300,3021.65)
CSA2_PCLK_4: R15.2 R18.2 U2.26 | length 3090.3
  Bottom Layer - SIG2 w8: U2.26@3339.37,3561.26 3310,3590.63 3310,3731 3222,3819 3036,3819 2924,3707 2924,3067.7 3100.7,2891 3855.3,2891 3939,2974.7 3939,3204 4016.5,3281.5 R18.2@4302,3281.5 R15.2@4355,3281.5
CSA2_SIN_4: R16.2 R17.2 U2.27 | length 2436
  Bottom Layer - SIG2 w6: U2.27@3280.32,3541.58 3127.95,3541.58 2957,3370.63 2957,3081.37 3114.37,2924 3841.63,2924 3906,2988.37 3906,3377 4010.26,3481.26 R17.2@4133,3481.26 R16.2@4186,3481.26
CSA2_SOUT: J10.4 U2.33 | length 2744.9
  Bottom Layer - SIG2 w6: U2.33@3280.32,3423.47 3032.47,3423.47 2973,3364 2973,3088 3121,2940 3835,2940 3890,2995 3890,3444 4027.26,3581.26 J10.4@4520,3581.26
GND: C1.2 C2.2 C3.2 C4.2 C5.2 C6.2 C7.2 C8.2 C9.2 C10.1 C11.1 C12.1 C13.1 C14.1 C15.1 C16.1 C17.1 C66.2 C67.2 C68.2 C69.2 C70.2 C71.2 C72.2 C73.2 C74.2 C75.1 C76.1 C77.1 C78.1 C79.1 C80.1 C81.1 C82.1 C131.2 C132.1 C133.1 C134.1 J2.2 J2.3 J2.4 J2.5 J3.5 J6.2 J7.2 J7.3 J7.4 J7.5 J9.2 J9.3 J9.4 J9.5 J10.5 J13.2 J14.1 J15.1 pad.1 pad.2 pad.3 pad.4 pad.5 R5.1 R6.1 R7.1 R11.2 R13.1 R17.1 R18.1 R19.1 R23.2 R24.1 TP1.1 TP1.2 TP1.3 TP1.4 TP1.5 TP1.6 TP1.7 TP1.8 TP1.9 TP1.10 TP1.11 TP1.12 TP1.13 TP1.14 TP1.15 TP1.16 TP2.17 TP2.18 TP2.19 TP2.20 TP2.21 TP2.22 TP2.23 TP2.24 TP2.25 TP2.26 TP2.27 TP2.28 TP2.29 TP2.30 TP2.31 TP2.32 TP3.1 TP3.2 TP3.3 TP3.4 TP3.5 TP3.6 TP3.7 TP3.8 TP3.9 TP3.10 TP3.11 TP3.12 TP3.13 TP3.14 TP3.15 TP3.16 TP4.17 TP4.18 TP4.19 TP4.20 TP4.21 TP4.22 TP4.23 TP4.24 TP4.25 TP4.26 TP4.27 TP4.28 TP4.29 TP4.30 TP4.31 TP4.32 U1.19 U1.21 U1.23 U1.29 U1.31 U1.34 U1.43 U1.52 U1.56 U1.59 U1.61 U1.63 U1.65 U1.68 U1.69 U2.19 U2.21 U2.23 U2.29 U2.31 U2.34 U2.43 U2.52 U2.56 U2.59 U2.61 U2.63 U2.65 U2.68 U2.69 | length 434.4
  Top Layer - SIG1 w20: R24.1@3940,3740 v1(3990,3740)
  Bottom Layer - SIG2 w20: R11.2@125,3113 v1(173,3113) ; v1(537.26,3417) R5.1@582,3417 ; v1(631.26,3516.74) R7.1@671,3516.74 ; v1(719.26,3617) R6.1@760,3617 ; R13.1@1760,3660 v1(1800,3660) ; R17.1@4133,3417.26 v1(4174.74,3417.26) ; R19.1@4216,3316 v1(4257.74,3316) ; R18.1@4302,3217.5 v1(4344.74,3217.5) ; v1(4585,3976) R23.2@4585,4021
  other v1: 1300,1700 1400,1700 1250,1750 1350,1750 1450,1750 1300,1800 1400,1800 1250,1850 1350,1850 1450,1850 1300,1900 1400,1900 1500,1900 3300,1900 3400,1900 3500,1900 1250,1950 1350,1950 1450,1950 1550,1950 3350,1950 3450,1950 3550,1950 3650,1950 3750,1950 1300,2000 1400,2000 1500,2000 1600,2000 3300,2000 3400,2000 3500,2000 3600,2000 3700,2000 3063,3198 880,3200 3105,3223 920,3225 880,3255 3063.03,3255 3067.99,3638.74 881.02,3643.74 3107.99,3663.74 921.02,3668.74 3067.99,3693.74 881.02,3698.74
NetC18_1: C18.1 TP2.1 | length 170.5
  Top Layer - SIG1 w6: C18.1@1956,4400.67 TP2.1@1955.99,4571.14
NetC18_2: C18.2 C29.1 U1.1 | length 799.6
  Top Layer - SIG1 w6: U1.1@1522.48,3771.89 1522.48,3785.48 1955,4218 v1@1955,4325 ; v1(1956,4326) C18.2@1956,4359.33
  Bottom Layer - SIG2 w6: v1(1956,4326) C29.1@1956,4360
NetC19_1: C19.1 U1.51 | length 579.2
  Top Layer - SIG1 w6: U1.51@1522.48,3350.63 1522.48,3334.52 1547.78,3309.22 1547.85,3309.22 1617,3240.07 1617,3090 1703,3004 C19.1@1703,2846.26
NetC19_2: C19.2 TP1.32 | length 564.9
  Top Layer - SIG1 w6: C19.2@1700,2800 1700,2770.74 1953.18,2517.56 TP1.32@1953.18,2340
NetC20_1: C20.1 TP2.2 | length 169.7
  Top Layer - SIG1 w6: C20.1@1877.25,4401.42 TP2.2@1877.25,4571.14
NetC20_2: C20.2 C28.1 U1.2 | length 718
  Top Layer - SIG1 w6: v1(1878,4325) C20.2@1878,4359.33
  Top Layer - SIG1 w8: U1.2@1502.8,3830.95 1502.79,3887.79 1876,4261 v1@1876,4325
  Bottom Layer - SIG2 w6: v1(1878,4325) C28.1@1878,4360
NetC21_1: C21.1 U1.50 | length 509.6
  Top Layer - SIG1 w6: U1.50@1502.8,3291.58 1502.8,3177.21 1658,3022 C21.1@1658,2846.26
NetC21_2: C21.2 TP1.31 | length 550.9
  Top Layer - SIG1 w6: C21.2@1655,2800 1655,2765.74 1874.44,2546.3 TP1.31@1874.44,2340
NetC22_1: C22.1 C40.2 U1.8 | length 571.4
  Top Layer - SIG1 w6: U1.8@1384.69,3830.95 1384.68,4243.68 1404,4263 v1@1404,4325 ; v1(1405,4325) C40.2@1405,4359.33
  Bottom Layer - SIG2 w6: v1(1405,4325) C22.1@1405,4360
NetC23_1: C23.1 C38.2 U1.7 | length 741.7
  Top Layer - SIG1 w6: U1.7@1404.37,3771.89 1432.48,3800 1514,3800 1530,3816 v1(1530,3872) ; v1(1483,4325) C38.2@1483,4359.33
  Bottom Layer - SIG2 w6: C23.1@1483,4360 v1(1483,4325) 1483,3919 v1(1530,3872)
NetC24_1: C24.1 C36.2 U1.6 | length 620.1
  Top Layer - SIG1 w6: U1.6@1424.06,3830.95 1424.05,3927.05 1561,4064 v1@1561,4325 ; v1(1562,4325) C36.2@1562,4359.33
  Bottom Layer - SIG2 w6: v1(1562,4325) C24.1@1562,4360
NetC25_1: C25.1 C34.2 U1.5 | length 733.7
  Top Layer - SIG1 w6: v1(1641,4325) C34.2@1641,4359.33
  Bottom Layer - SIG2 w6: U1.5@1443.74,3771.89 1471.85,3800 1523,3800 1570,3847 1570,4071 1640,4141 v1@1640,4325 ; v1(1641,4325) C25.1@1641,4360
NetC26_1: C26.1 C32.2 U1.4 | length 670.6
  Top Layer - SIG1 w6: v1(1720,4325) C32.2@1720,4360
  Top Layer - SIG1 w8: U1.4@1463.43,3830.95 1463.42,3906.42 1719,4162 v1@1719,4325
  Bottom Layer - SIG2 w6: v1(1720,4325) C26.1@1720,4360.67
NetC27_1: C27.1 C30.2 U1.3 | length 836
  Top Layer - SIG1 w6: v1(1799,4325) C30.2@1799,4358.33
  Bottom Layer - SIG2 w6: U1.3@1483.11,3771.89 1509,3746 1566,3746 1605,3785 1605,4049 1798,4242 v1@1798,4325 ; v1(1799,4325) C27.1@1799,4359
NetC30_1: C30.1 TP2.3 | length 171
  Top Layer - SIG1 w6: C30.1@1798.51,4400.16 TP2.3@1798.51,4571.14
NetC31_1: C31.1 U1.49 | length 623.2
  Top Layer - SIG1 w6: C31.1@1613,2846.26 1614,2847.26 v1(1614,2988)
  Bottom Layer - SIG2 w6: U1.49@1483.11,3350.63 1507.92,3375.44 1532.76,3375.44 1549,3359.2 1549,3303.63 1614,3238.63 v1(1614,2988)
NetC31_2: C31.2 TP1.30 | length 536.9
  Top Layer - SIG1 w6: C31.2@1610,2800 1610,2760.74 1795.7,2575.04 TP1.30@1795.7,2340
NetC32_1: C32.1 TP2.4 | length 169.6
  Top Layer - SIG1 w6: C32.1@1719.77,4401.57 TP2.4@1719.77,4571.14
NetC33_1: C33.1 U1.48 | length 488.6
  Top Layer - SIG1 w6: U1.48@1463.43,3291.58 1463.43,3176.58 1568,3072 C33.1@1568,2846.26
NetC33_2: C33.2 TP1.29 | length 522.9
  Top Layer - SIG1 w6: C33.2@1565,2800 1565,2755.74 1716.96,2603.78 TP1.29@1716.96,2340
NetC34_1: C34.1 TP2.5 | length 170.4
  Top Layer - SIG1 w6: C34.1@1641,4400.67 TP2.5@1641.03,4571.14
NetC35_1: C35.1 U1.47 | length 594
  Top Layer - SIG1 w6: C35.1@1523,2846.26 1524,2847.26 v1(1524,2989)
  Bottom Layer - SIG2 w6: U1.47@1443.74,3350.63 1474.37,3320 1510,3320 1567.5,3262.5 1567.5,3139.76 1522.37,3094.63 v1@1522.37,2990.63
NetC35_2: C35.2 TP1.28 | length 509
  Top Layer - SIG1 w6: C35.2@1520,2800 1520,2750.74 1638.22,2632.52 TP1.28@1638.22,2340
NetC36_1: C36.1 TP2.6 | length 170.2
  Top Layer - SIG1 w6: C36.1@1562.29,4400.96 TP2.6@1562.29,4571.14
NetC37_1: C37.1 U1.46 | length 467.7
  Top Layer - SIG1 w6: U1.46@1424.06,3291.58 1424.06,3175.95 1478,3122 C37.1@1478,2846.26
NetC37_2: C37.2 TP1.27 | length 495
  Top Layer - SIG1 w6: C37.2@1475,2800 1475,2745.74 1559.48,2661.26 TP1.27@1559.48,2340
NetC38_1: C38.1 TP2.7 | length 170.7
  Top Layer - SIG1 w6: C38.1@1483,4400.67 1483.55,4401.22 TP2.7@1483.55,4571.14
NetC39_1: C39.1 U1.45 | length 651.8
  Top Layer - SIG1 w6: U1.45@1404.37,3350.63 1434,3321 1513,3321 1542,3292 v1(1542,3250) ; C39.1@1433,2846.26 v1(1433,2989)
  Bottom Layer - SIG2 w6: v1@1431.37,2990.63 1431.37,3139.37 v1(1542,3250)
NetC39_2: C39.2 TP1.26 | length 481
  Top Layer - SIG1 w6: C39.2@1430,2800 1430,2740.74 1480.74,2690 TP1.26@1480.74,2340
NetC40_1: C40.1 TP2.8 | length 170.5
  Top Layer - SIG1 w6: TP2.8@1404.81,4571.14 1404.81,4400.86 C40.1@1405,4400.67
NetC41_1: C41.1 U1.44 | length 446.3
  Top Layer - SIG1 w6: U1.44@1384.69,3291.58 1384.69,2848.58 C41.1@1387,2846.26
NetC41_2: C41.2 TP1.25 | length 467
  Top Layer - SIG1 w6: C41.2@1385,2800 1385,2740 1402,2723 TP1.25@1402,2340
NetC42_1: C42.1 TP2.9 | length 170.2
  Top Layer - SIG1 w6: C42.1@1326,4401 1326.07,4401.07 TP2.9@1326.07,4571.14
NetC42_2: C42.2 C52.2 U1.10 | length 571.7
  Top Layer - SIG1 w6: C42.2@1326,4359.66 v1(1326,4325) 1326,4263 1345.32,4243.68 U1.10@1345.32,3830.95
  Bottom Layer - SIG2 w6: v1(1326,4325) C52.2@1326,4360
NetC43_1: C43.1 U1.42 | length 446.7
  Top Layer - SIG1 w6: C43.1@1342,2846.26 1345.32,2849.58 U1.42@1345.32,3291.58
NetC43_2: C43.2 TP1.24 | length 467
  Top Layer - SIG1 w6: TP1.24@1325,2346.26 1325,2725 1342,2742 C43.2@1342,2806.26
NetC44_1: C44.1 TP2.10 | length 170.6
  Top Layer - SIG1 w6: C44.1@1247,4400.67 1247.33,4401 TP2.10@1247.33,4571.14
NetC44_2: C44.2 C53.2 U1.11 | length 741.7
  Top Layer - SIG1 w6: v1(1200,3872) 1200,3816 1216,3800 1297.52,3800 U1.11@1325.63,3771.89 ; v1(1247,4325) C44.2@1247,4359.33
  Bottom Layer - SIG2 w6: v1(1200,3872) 1247,3919 v1(1247,4325) C53.2@1247,4360
NetC45_1: C45.1 U1.41 | length 659.4
  Top Layer - SIG1 w6: v1(1180,3250) 1180,3284 1217,3321 1296,3321 U1.41@1325.63,3350.63 ; C45.1@1297,2846.26 v1(1297,2989)
  Bottom Layer - SIG2 w6: v1(1180,3250) 1297,3133 v1(1297,2989)
NetC45_2: C45.2 TP1.23 | length 481
  Top Layer - SIG1 w6: TP1.23@1246.26,2346.26 1246.26,2696.26 1297,2747 C45.2@1297,2806.26
NetC46_1: C46.1 TP2.11 | length 170.6
  Top Layer - SIG1 w6: TP2.11@1168.59,4571.14 1168.59,4401.08 C46.1@1169,4400.67
NetC46_2: C46.2 C54.2 U1.12 | length 620.1
  Top Layer - SIG1 w6: C46.2@1169,4359.33 v1(1169,4325) 1169,4064 1305.95,3927.05 U1.12@1305.95,3830.95
  Bottom Layer - SIG2 w6: v1(1169,4325) C54.2@1169,4360
NetC47_1: C47.1 U1.40 | length 467.7
  Top Layer - SIG1 w6: C47.1@1252,2846.26 1252,3122 1305.95,3175.95 U1.40@1305.95,3291.58
NetC47_2: C47.2 TP1.22 | length 495
  Top Layer - SIG1 w6: TP1.22@1167.52,2346.26 1167.52,2667.52 1252,2752 C47.2@1252,2806.26
NetC48_1: C48.1 TP2.12 | length 170.5
  Top Layer - SIG1 w6: TP2.12@1089.85,4571.14 1089.85,4400.82 C48.1@1090,4400.67
NetC48_2: C48.2 C55.2 U1.13 | length 724.3
  Top Layer - SIG1 w6: v1(1090,4325) C48.2@1090,4359.33
  Bottom Layer - SIG2 w6: C55.2@1090,4360 v1(1090,4325) 1090,4141 1160,4071 1160,3863.06 1223.06,3800 1258.15,3800 U1.13@1286.26,3771.89
NetC49_1: C49.1 U1.39 | length 625.6
  Top Layer - SIG1 w6: v1(1206,2989) 1206,2847.26 C49.1@1207,2846.26
  Bottom Layer - SIG2 w6: v1(1206,2989) 1206,3093 1154.5,3144.5 1154.5,3295.5 1184,3325 1260.63,3325 U1.39@1286.26,3350.63
NetC49_2: C49.2 TP1.21 | length 509
  Top Layer - SIG1 w6: TP1.21@1088.78,2346.26 1088.78,2638.78 1207,2757 C49.2@1207,2806.26
NetC50_1: C50.1 TP2.13 | length 170.5
  Top Layer - SIG1 w6: C50.1@1011,4400.67 1011.11,4400.78 TP2.13@1011.11,4571.14
NetC50_2: C50.2 C56.2 U1.14 | length 669.2
  Top Layer - SIG1 w6: v1(1011,4325) C50.2@1011,4359.33
  Top Layer - SIG1 w8: v1(1011,4325) 1011,4162 1266.58,3906.42 U1.14@1266.58,3830.95
  Bottom Layer - SIG2 w6: v1(1011,4325) C56.2@1011,4360
NetC51_1: C51.1 U1.38 | length 488.6
  Top Layer - SIG1 w6: C51.1@1162,2846.26 1162,3072 1266.58,3176.58 U1.38@1266.58,3291.58
NetC51_2: C51.2 TP1.20 | length 522.9
  Top Layer - SIG1 w6: TP1.20@1010.04,2346.26 1010.04,2610.04 1162,2762 C51.2@1162,2806.26
NetC57_2: C57.2 C60.2 U1.15 | length 817.9
  Top Layer - SIG1 w6: v1(932,4325) C60.2@932,4359.33
  Bottom Layer - SIG2 w6: C57.2@932,4360 v1(932,4325) 932,4242 1125,4049 1125,3875.44 1170,3830.44 1170,3774.32 1198.32,3746 1221,3746 U1.15@1246.89,3771.89
NetC58_2: C58.2 C62.2 U1.16 | length 718
  Top Layer - SIG1 w6: v1(854,4325) C62.2@854,4359.33
  Top Layer - SIG1 w8: v1(854,4325) 854,4261 1227.21,3887.79 U1.16@1227.21,3830.95
  Bottom Layer - SIG2 w6: v1(854,4325) C58.2@854,4360
NetC59_2: C59.2 C64.2 U1.17 | length 801.6
  Top Layer - SIG1 w6: C64.2@775,4359.33 v1(775,4325) 775,4218 1207.52,3785.48 U1.17@1207.52,3771.89
  Bottom Layer - SIG2 w6: v1(775,4325) C59.2@775,4360
NetC60_1: C60.1 TP2.14 | length 170.6
  Top Layer - SIG1 w6: C60.1@932,4400.67 932.37,4401.04 TP2.14@932.37,4571.14
NetC61_1: C61.1 U1.37 | length 626.9
  Top Layer - SIG1 w6: v1(1116,2988) 1116,2847.26 C61.1@1117,2846.26
  Bottom Layer - SIG2 w6: v1(1116,2988) 1116,3297 1197,3378 1219.52,3378 U1.37@1246.89,3350.63
NetC61_2: C61.2 TP1.19 | length 536.9
  Top Layer - SIG1 w6: TP1.19@931.3,2346.26 931.3,2581.3 1117,2767 C61.2@1117,2806.26
NetC62_1: C62.1 TP2.15 | length 170.6
  Top Layer - SIG1 w6: TP2.15@853.63,4571.14 853.63,4401.04 C62.1@854,4400.67
NetC63_1: C63.1 U1.36 | length 509.6
  Top Layer - SIG1 w6: C63.1@1072,2846.26 1072,3022 1227.21,3177.21 U1.36@1227.21,3291.58
NetC63_2: C63.2 TP1.18 | length 550.9
  Top Layer - SIG1 w6: TP1.18@852.56,2346.26 852.56,2552.56 1072,2772 C63.2@1072,2806.26
NetC64_1: C64.1 TP2.16 | length 170.7
  Top Layer - SIG1 w6: C64.1@775,4400.67 774.89,4400.78 TP2.16@774.89,4571.14 TP2.16@775,4571.02
NetC65_1: C65.1 U1.35 | length 579.1
  Top Layer - SIG1 w6: C65.1@1027,2846.26 1027,3004 1113,3090 1113,3256.11 U1.35@1207.52,3350.63
NetC65_2: C65.2 TP1.17 | length 564.9
  Top Layer - SIG1 w6: TP1.17@773.82,2346.26 773.82,2523.82 1027,2777 C65.2@1027,2806.26
NetC83_1: C83.1 TP4.1 | length 170.5
  Top Layer - SIG1 w6: C83.1@4141.1,4397.69 TP4.1@4141.1,4568.15
NetC83_2: C83.2 C94.1 U2.1 | length 799.6
  Top Layer - SIG1 w6: U2.1@3707.48,3771.89 3707.48,3785.48 4140,4218 v1@4140,4325 ; v1(4141,4326) C83.2@4141,4359.33
  Bottom Layer - SIG2 w6: v1(4141,4326) C94.1@4141,4360
NetC84_1: C84.1 U2.51 | length 579.1
  Top Layer - SIG1 w6: U2.51@3707.48,3350.63 3707.48,3338.07 3802,3243.55 3802,3090 3888,3004 C84.1@3888,2846.26
NetC84_2: C84.2 TP3.32 | length 564.9
  Top Layer - SIG1 w6: C84.2@3885,2800 3885,2770.74 4138.18,2517.56 TP3.32@4138.18,2340
NetC85_1: C85.1 TP4.2 | length 169.7
  Top Layer - SIG1 w6: C85.1@4062.36,4398.43 TP4.2@4062.36,4568.15
NetC85_2: C85.2 C93.1 U2.2 | length 718
  Top Layer - SIG1 w6: v1(4063,4325) C85.2@4063,4359.33
  Top Layer - SIG1 w8: U2.2@3687.8,3830.95 3687.79,3887.79 4061,4261 v1@4061,4325
  Bottom Layer - SIG2 w6: v1(4063,4325) C93.1@4063,4360
NetC86_1: C86.1 U2.50 | length 509.6
  Top Layer - SIG1 w6: U2.50@3687.8,3291.58 3687.8,3177.21 3843,3022 C86.1@3843,2846.26
NetC86_2: C86.2 TP3.31 | length 550.9
  Top Layer - SIG1 w6: C86.2@3840,2800 3840,2765.74 4059.44,2546.3 TP3.31@4059.44,2340
NetC87_1: C87.1 C105.2 U2.8 | length 571.3
  Top Layer - SIG1 w6: U2.8@3569.69,3830.95 3569.68,4243.68 3589,4263 v1@3589,4325 ; v1(3590,4325) C105.2@3590,4359.25 C105.2@3590,4359.25
  Bottom Layer - SIG2 w6: v1(3590,4325) C87.1@3590,4359.92
NetC88_1: C88.1 C103.2 U2.7 | length 740.7
  Top Layer - SIG1 w6: U2.7@3589.37,3771.89 3617.48,3800 3699,3800 3715,3816 v1(3715,3872) ; v1(3668,4325) C103.2@3668,4359.33
  Bottom Layer - SIG2 w6: v1(3668,4325) 3668,3919 v1(3715,3872) ; v1@3669,4326 C88.1@3669,4360
NetC89_1: C89.1 C101.2 U2.6 | length 620.1
  Top Layer - SIG1 w6: U2.6@3609.06,3830.95 3609.05,3927.05 3746,4064 v1@3746,4325 ; v1(3747,4325) C101.2@3747,4359.33
  Bottom Layer - SIG2 w6: v1(3747,4325) C89.1@3747,4360
NetC90_1: C90.1 C99.2 U2.5 | length 733.7
  Top Layer - SIG1 w6: v1(3826,4325) C99.2@3826,4359.33
  Bottom Layer - SIG2 w6: U2.5@3628.74,3771.89 3656.85,3800 3708,3800 3755,3847 3755,4071 3825,4141 v1@3825,4325 ; v1(3826,4325) C90.1@3826,4360
NetC91_1: C91.1 C97.2 U2.4 | length 668.9
  Top Layer - SIG1 w6: v1(3905,4325) C97.2@3905,4360
  Top Layer - SIG1 w8: U2.4@3648.43,3830.95 3648.42,3906.42 3904,4162 v1@3904,4325
  Bottom Layer - SIG2 w6: v1@3904,4326 C91.1@3904,4360
NetC92_1: C92.1 C95.2 U2.3 | length 834.1
  Top Layer - SIG1 w6: v1(3984,4325) C95.2@3984,4358.33
  Bottom Layer - SIG2 w6: U2.3@3668.11,3771.89 3694,3746 3716.68,3746 3746,3746 3790,3790 3790,4049 3983,4242 v1@3983,4325 ; v1(3984,4325) C92.1@3984,4360
NetC95_1: C95.1 TP4.3 | length 171
  Top Layer - SIG1 w6: C95.1@3983.62,4397.17 TP4.3@3983.62,4568.15
NetC96_1: C96.1 U2.49 | length 625.6
  Top Layer - SIG1 w6: C96.1@3798,2846.26 3799,2847.26 v1(3799,2988)
  Bottom Layer - SIG2 w6: U2.49@3666.48,3352.26 3693.85,3379.63 3713.57,3379.63 3732.29,3360.91 3732.29,3313.26 3775.83,3269.72 3776.28,3269.72 3797.37,3248.63 v1@3797.37,2989.63
NetC96_2: C96.2 TP3.30 | length 536.9
  Top Layer - SIG1 w6: C96.2@3795,2800 3795,2760.74 3980.7,2575.04 TP3.30@3980.7,2340
NetC97_1: C97.1 TP4.4 | length 169.6
  Top Layer - SIG1 w6: C97.1@3904.88,4398.58 TP4.4@3904.88,4568.15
